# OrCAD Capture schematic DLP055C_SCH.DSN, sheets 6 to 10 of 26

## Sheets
6 P21 - Ballast Connection: size A3
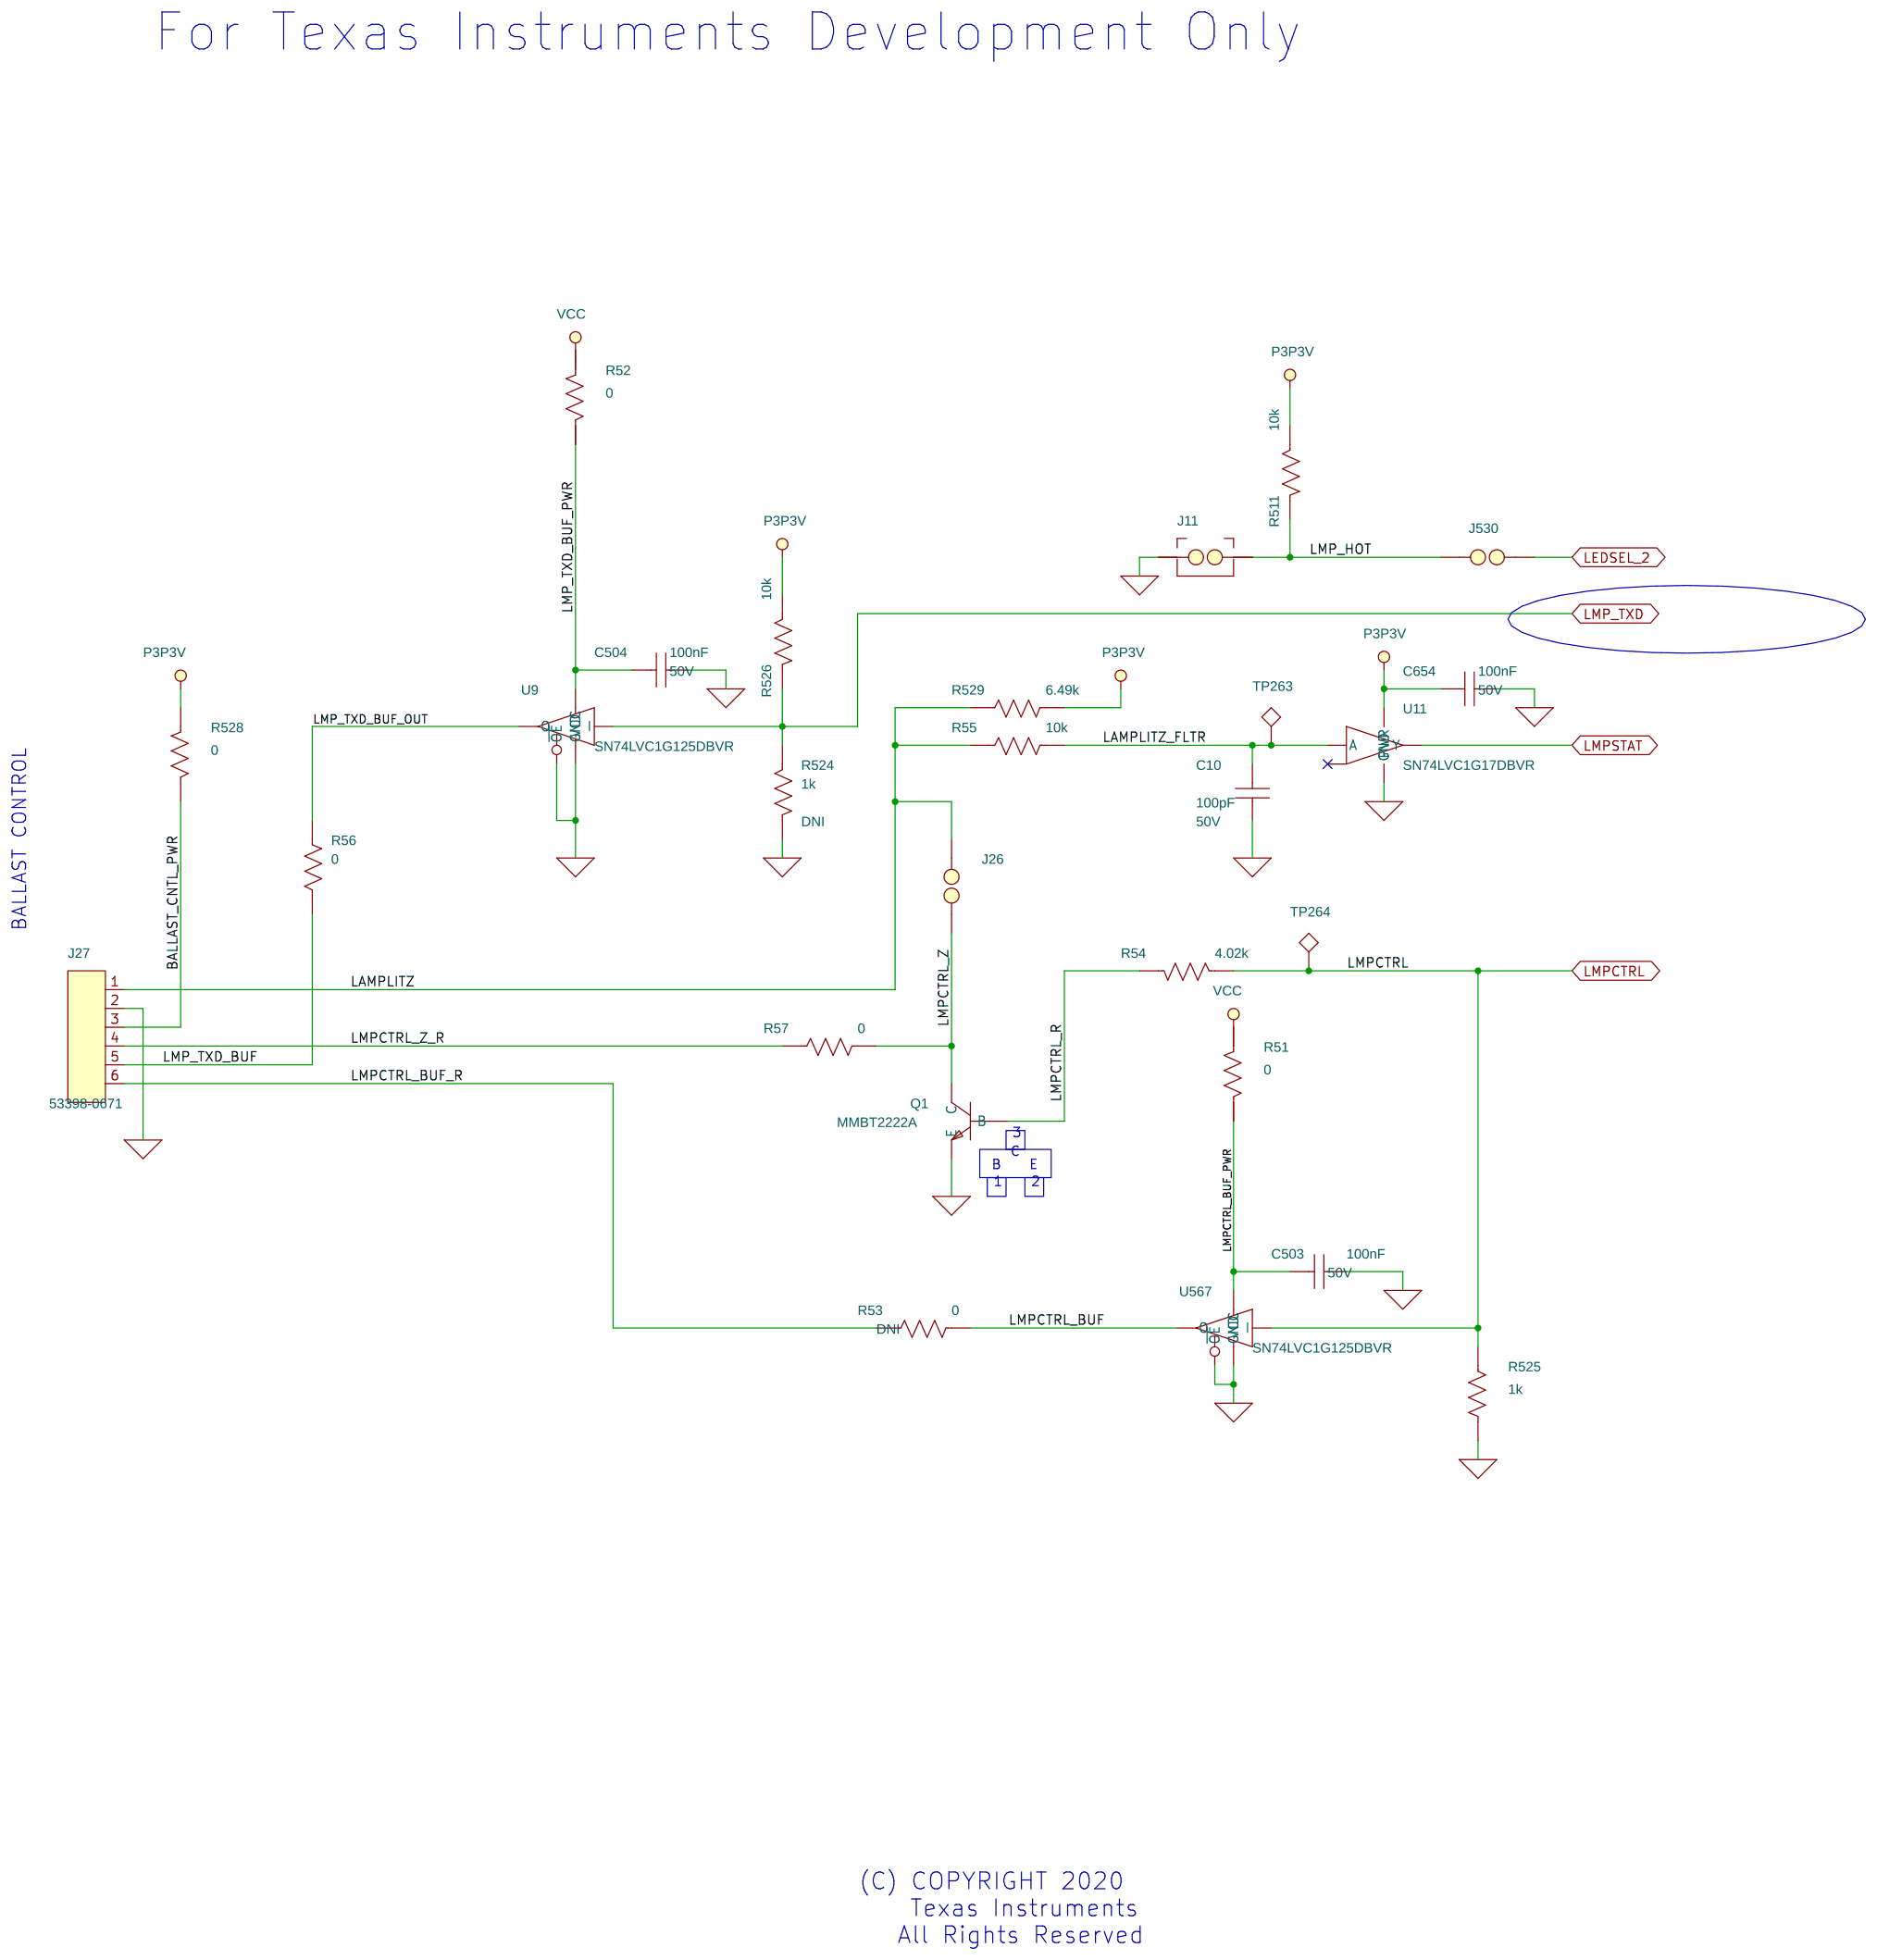
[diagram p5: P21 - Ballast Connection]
7 P19 - VIN & POWER SEQ: size D
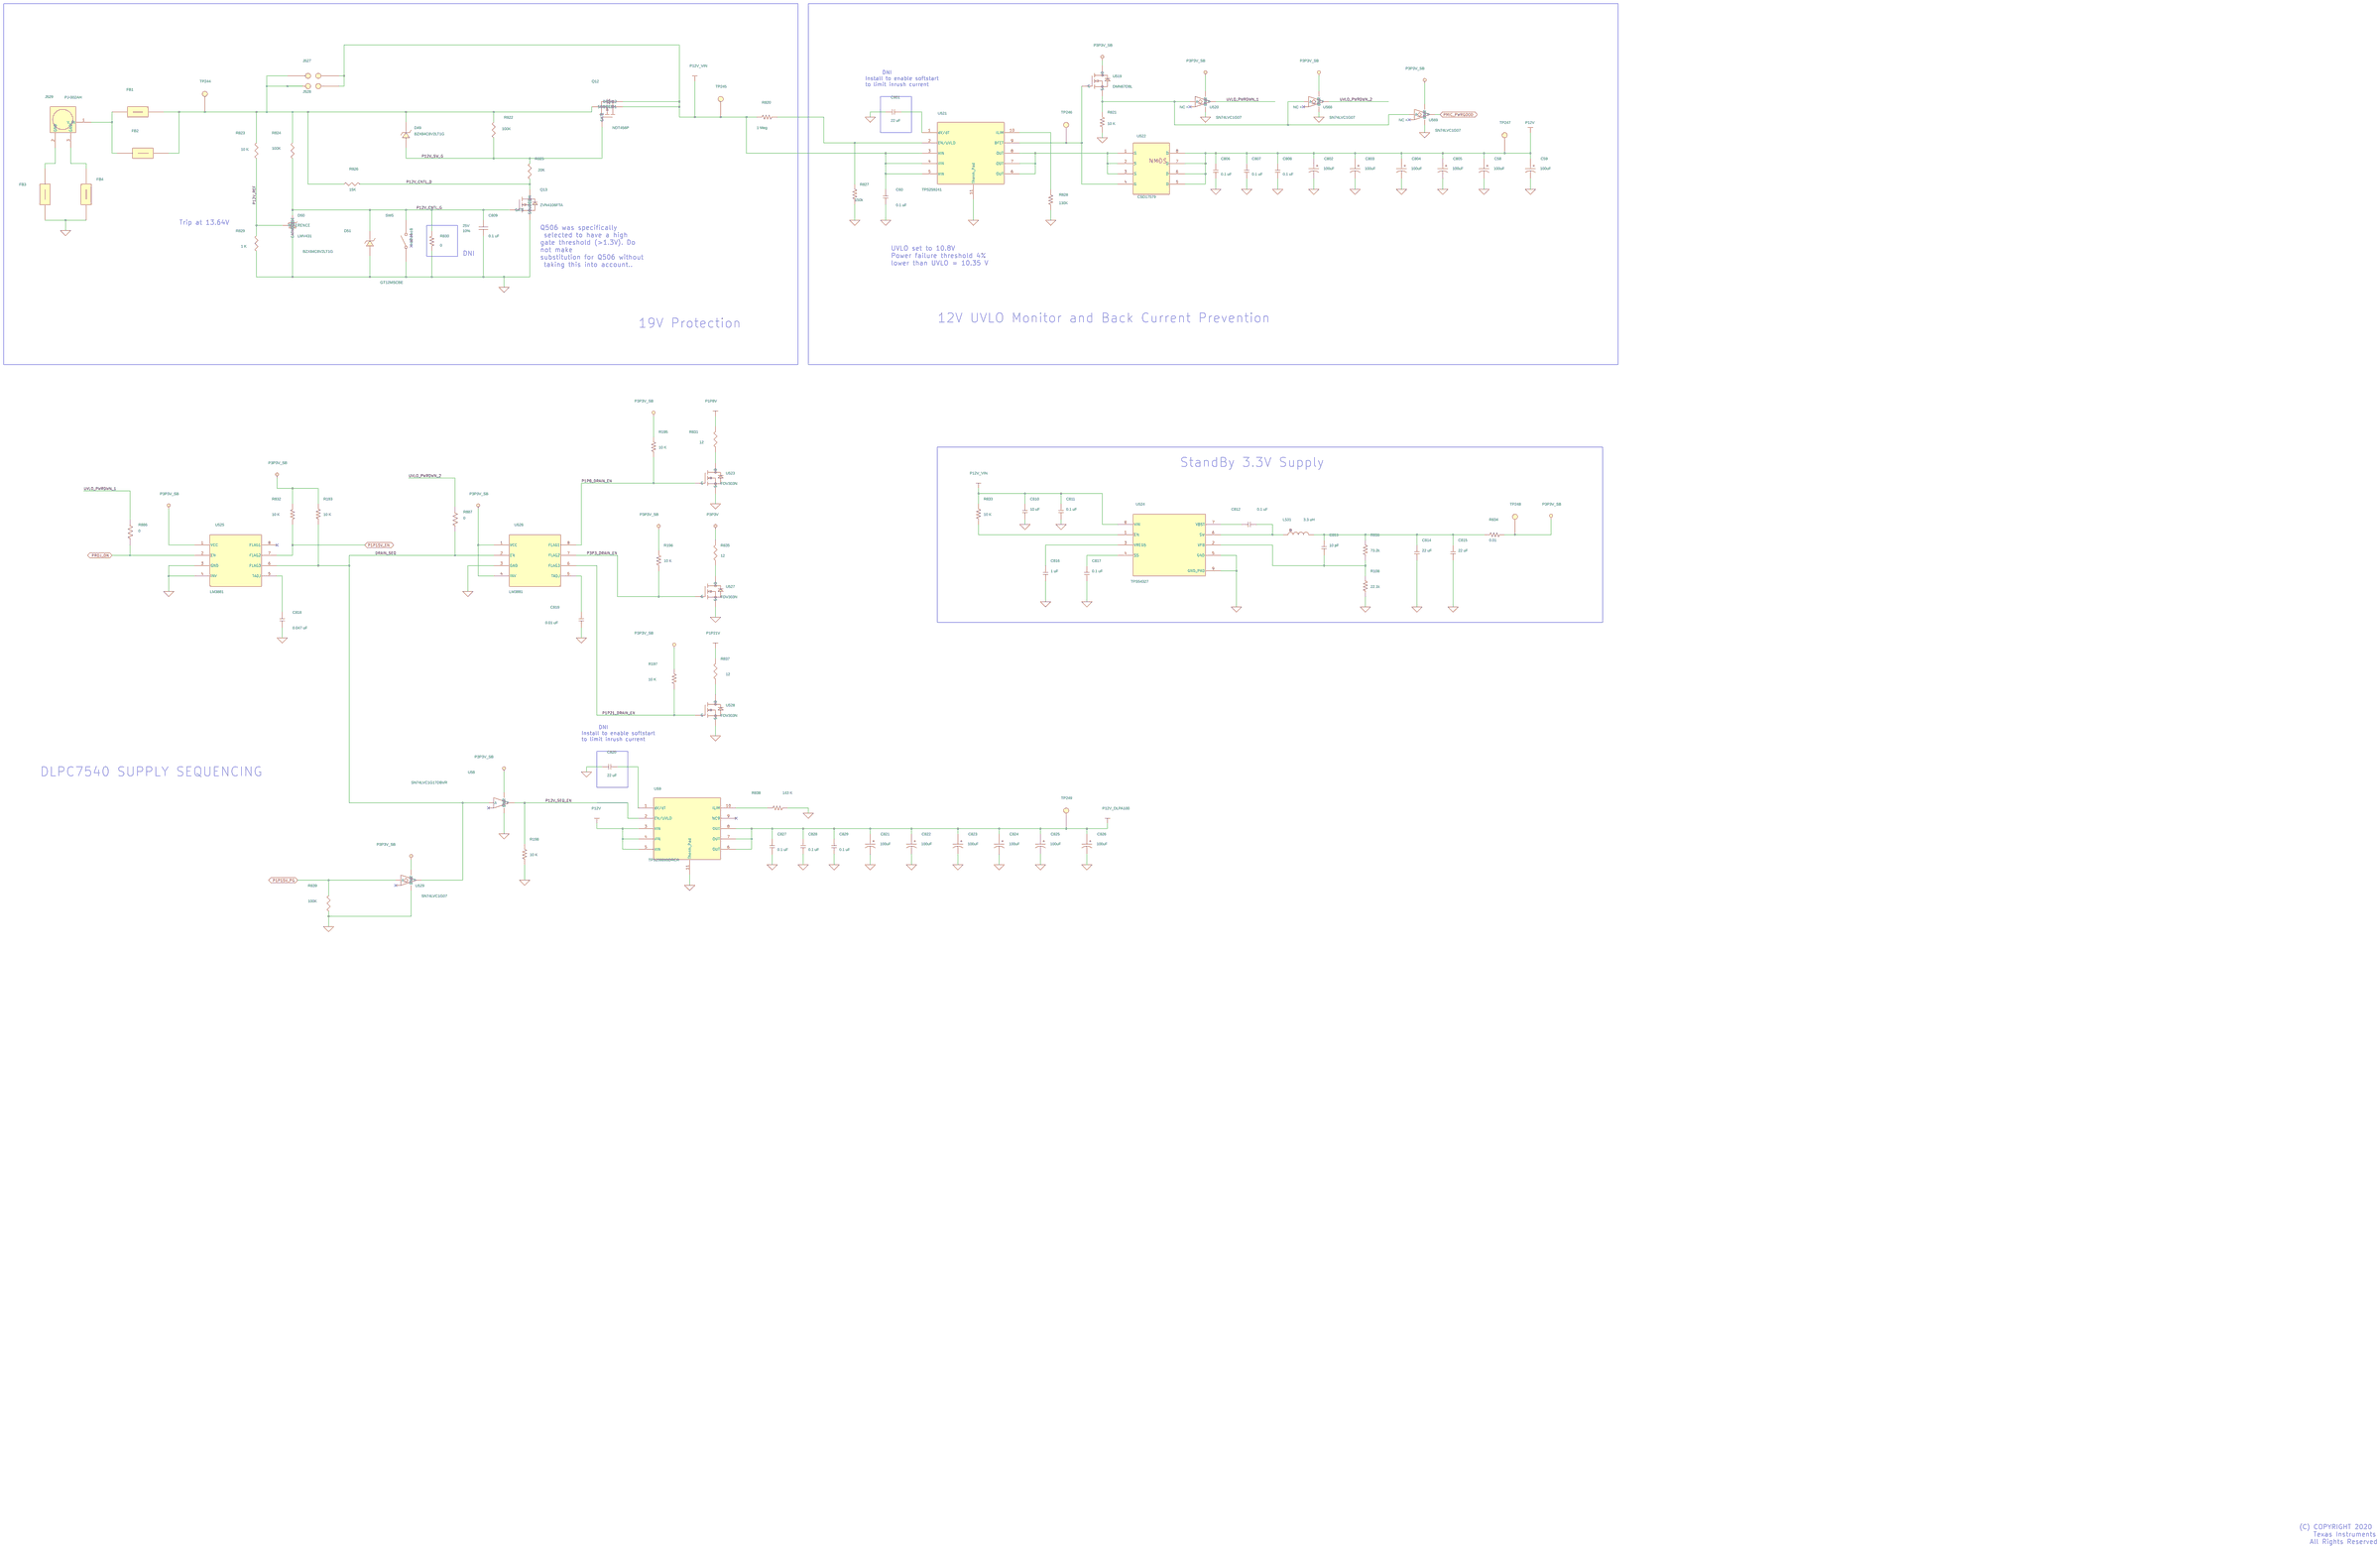
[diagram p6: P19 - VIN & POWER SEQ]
8 P17 - DLPA100 #2: size D
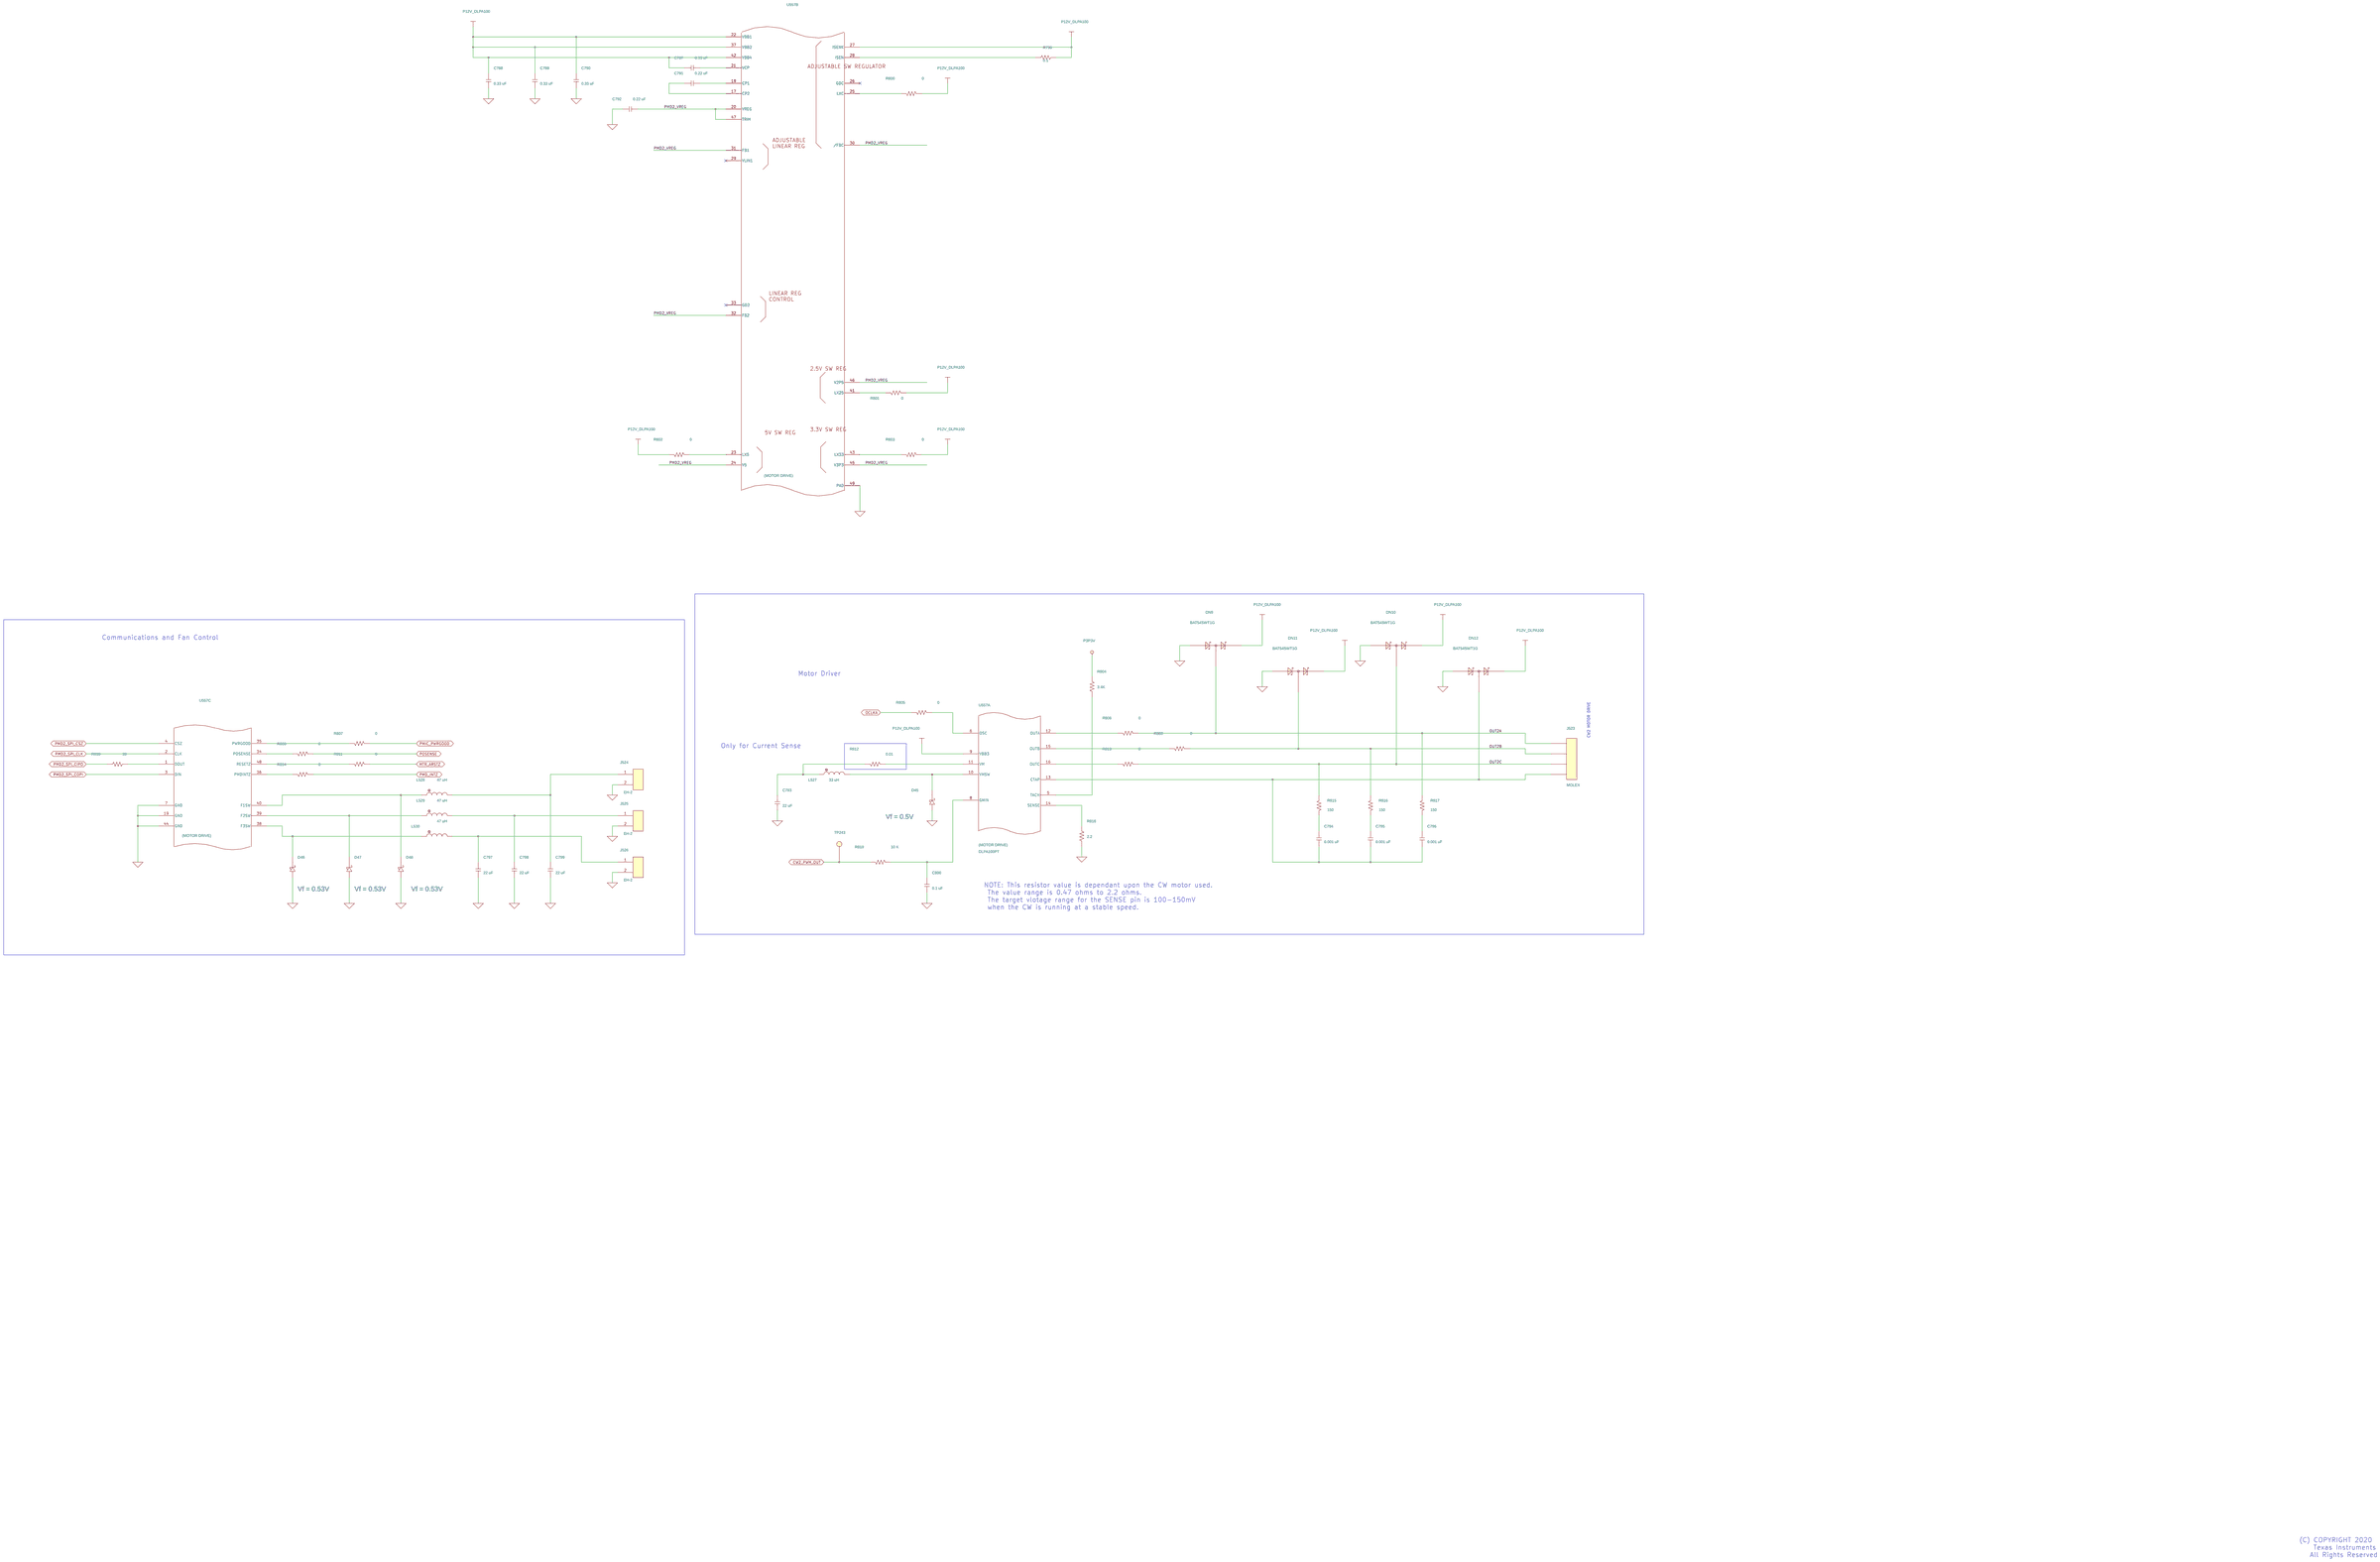
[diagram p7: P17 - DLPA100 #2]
9 P16 - DLPA100 #1: size D
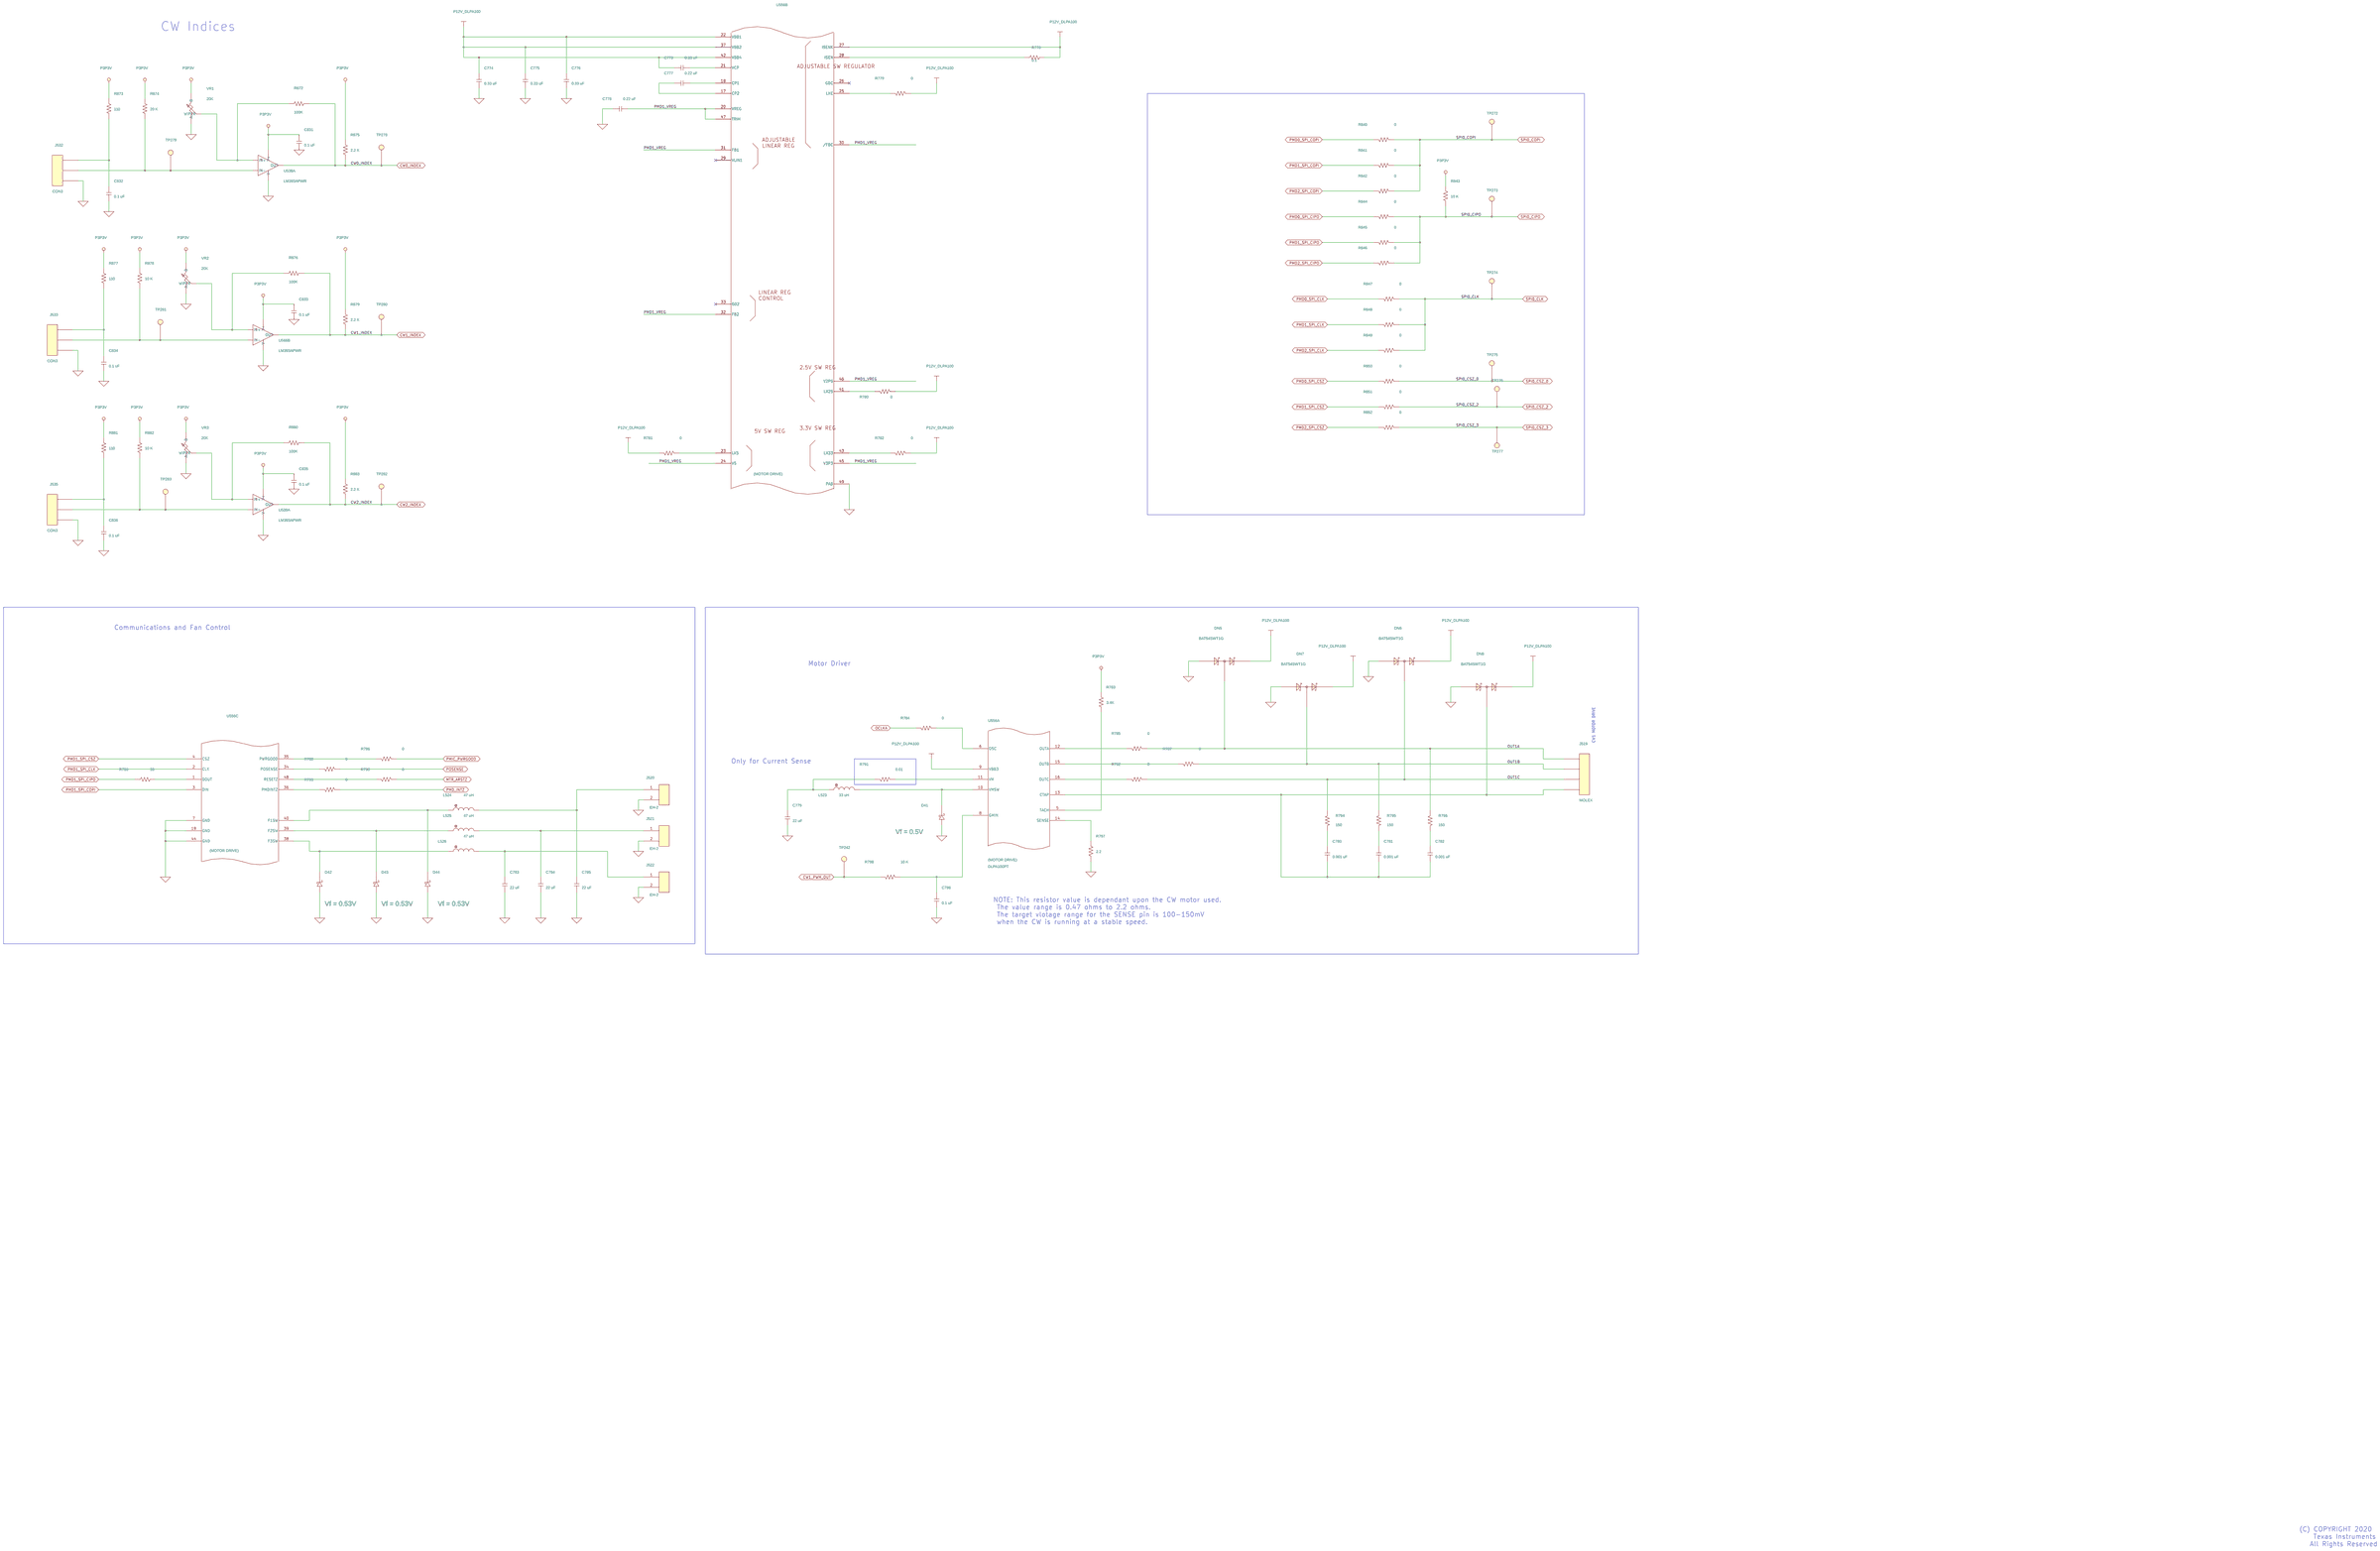
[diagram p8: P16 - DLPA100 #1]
10 P15 - DLPA100 #0: size D
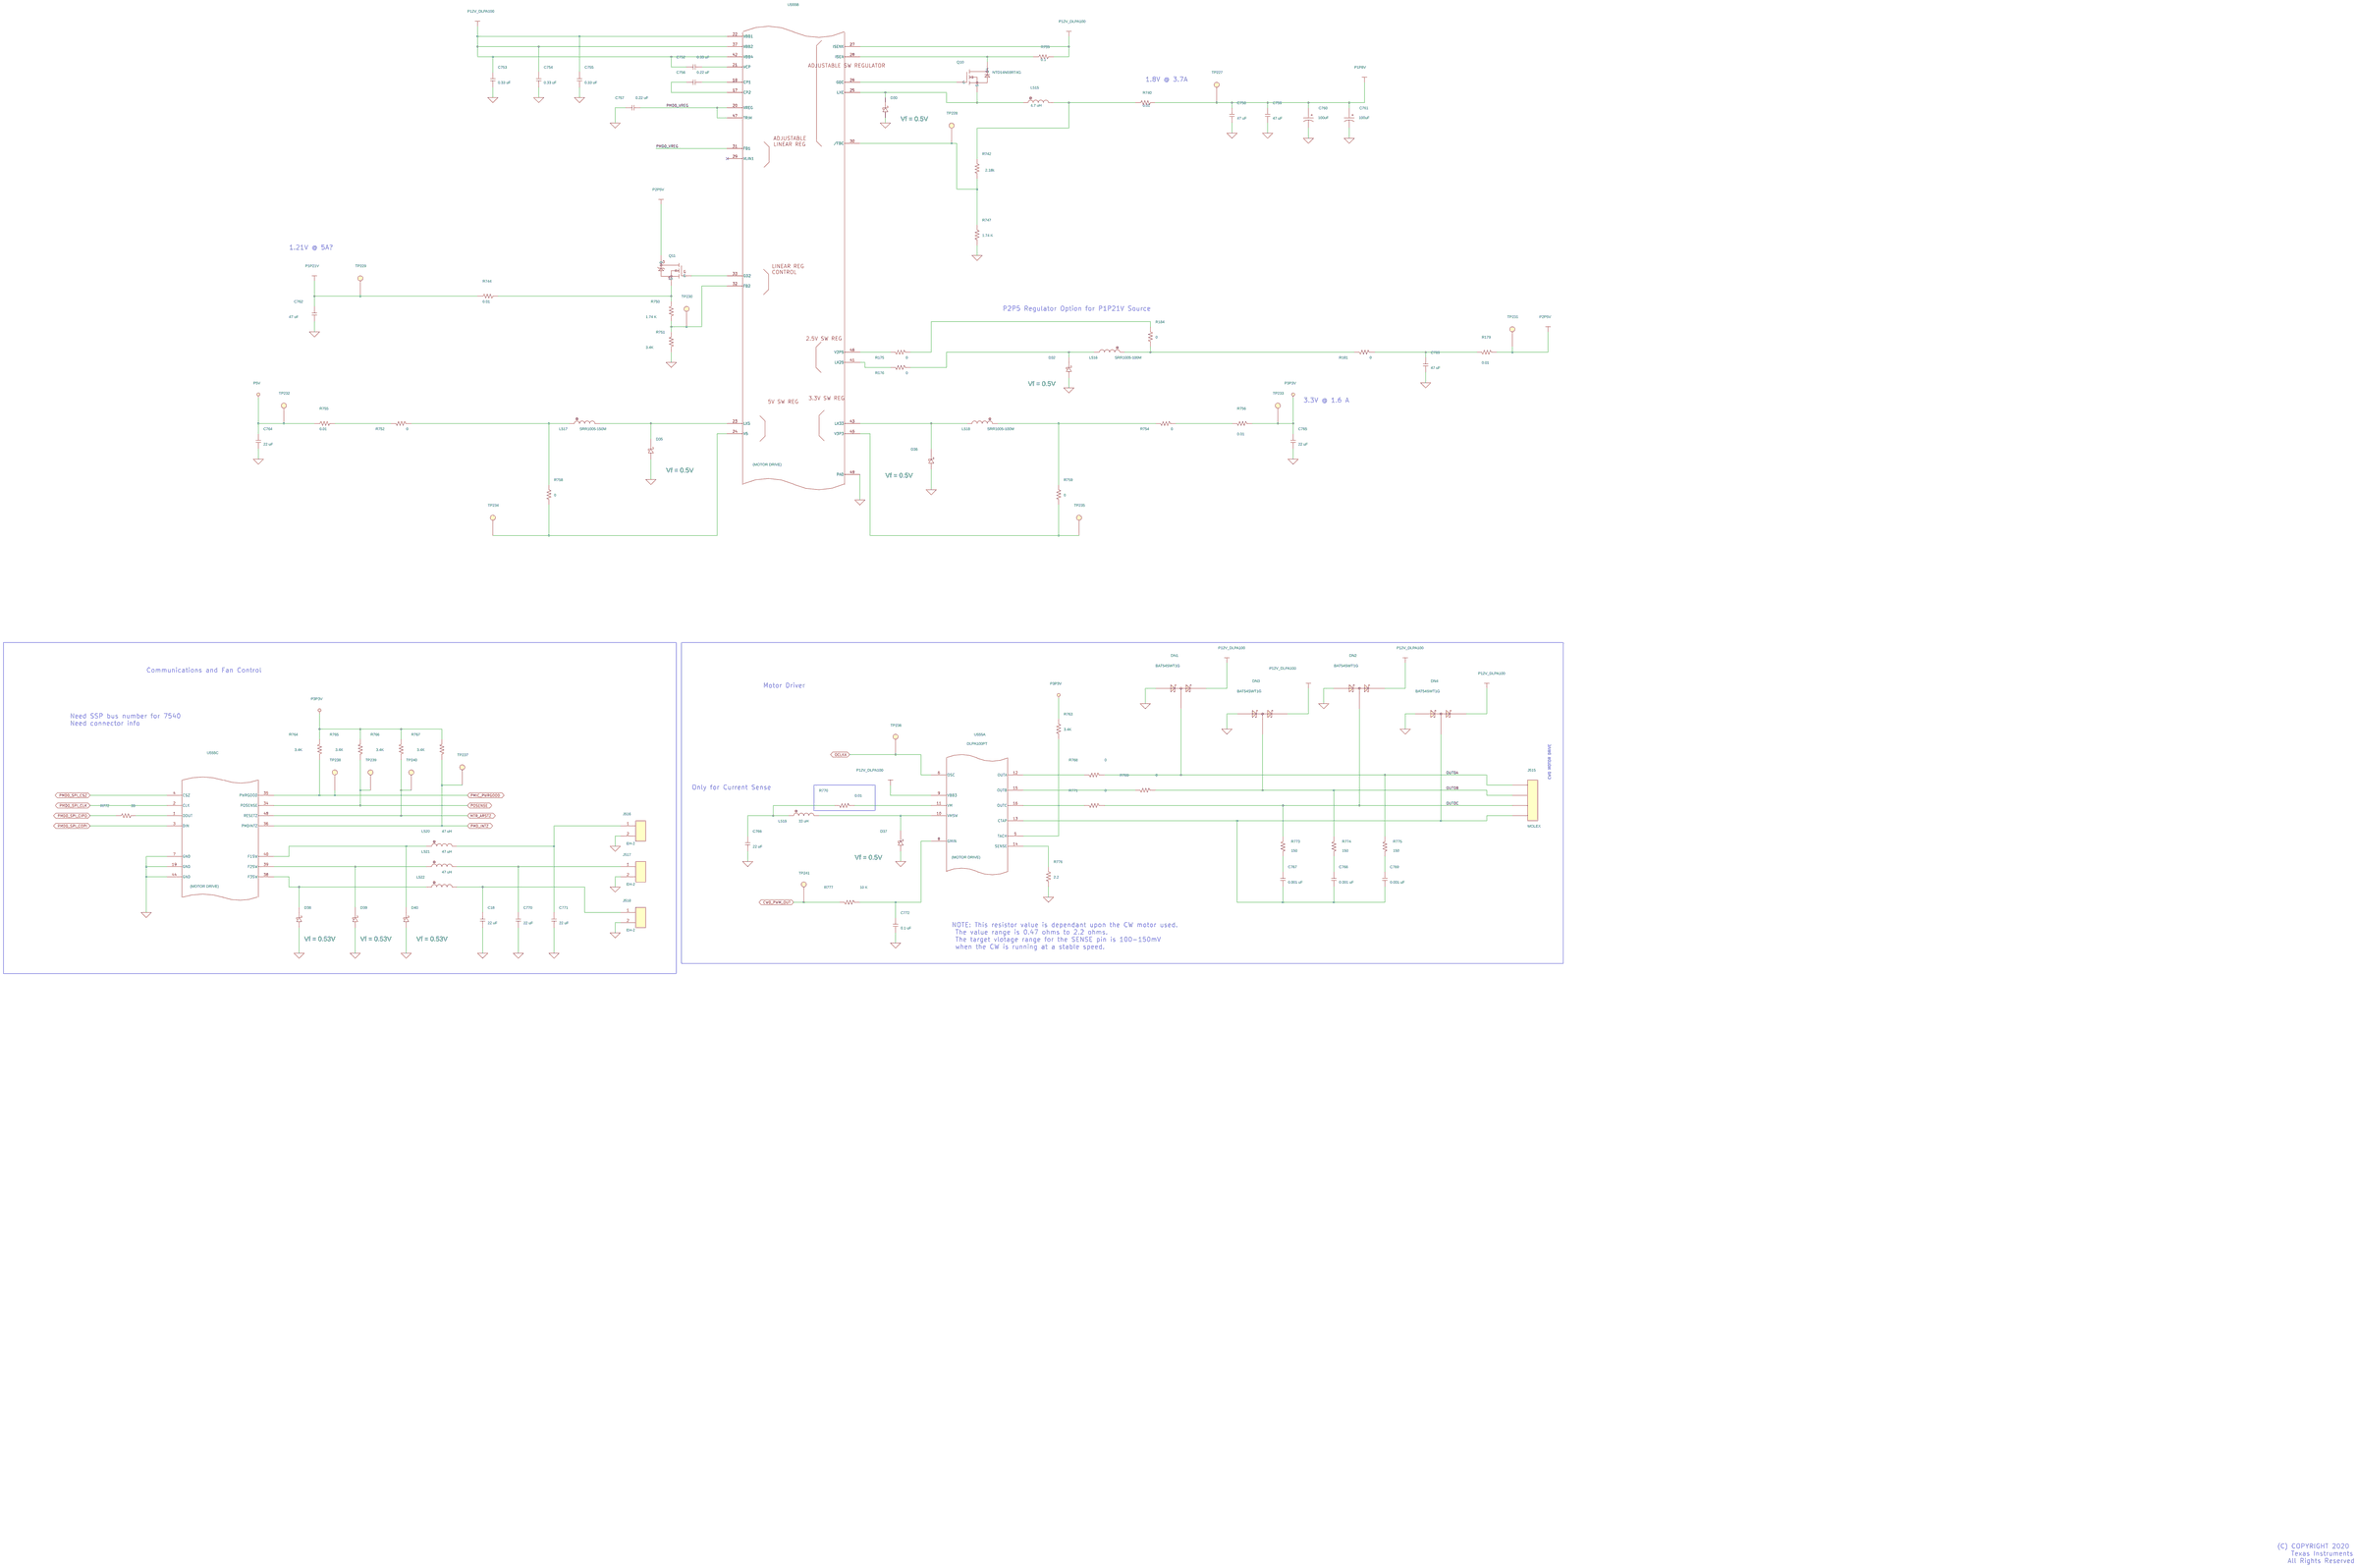
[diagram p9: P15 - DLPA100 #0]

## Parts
sheet P15 - DLPA100 #0
C18  22 uF  [0805]
C752  0.33 uF  [0805]
C753  0.33 uF  [0805]
C754  0.33 uF  [0805]
C755  0.33 uF  [0805]
C756  0.22 uF  [0603]
C757  0.22 uF  [0603]
C758  47 uF  [1206]
C759  47 uF  [1206]
C760  100uF  [7343]
C761  100uF  [7343]
C762  47 uF  [1206]
C763  47 uF  [1206]
C764  22 uF  [0805]
C765  22 uF  [0805]
C766  22 uF  [0805]
C767  0.001 uF  [0603]
C768  0.001 uF  [0603]
C769  0.001 uF  [0603]
C770  22 uF  [0805]
C771  22 uF  [0805]
C772  0.1 uF  [0603]
D30  B220A-13-F  [DIO-SMA_DIO-MOD]
D32  B220A-13-F  [DIO-SMA_DIO-MOD]
D35  B220A-13-F  [DIO-SMA_DIO-MOD]
D36  B220A-13-F  [DIO-SMA_DIO-MOD]
D37  B220A-13-F  [DIO-SMA_DIO-MOD]
D38  B220A-13-F  [DIO-SMA_DIO-MOD]
D39  B220A-13-F  [DIO-SMA_DIO-MOD]
D40  B220A-13-F  [DIO-SMA_DIO-MOD]
DN1  BAT54SWT1G  [SOT-323_SC70_ONSEMI_MOD]
DN2  BAT54SWT1G  [SOT-323_SC70_ONSEMI_MOD]
DN3  BAT54SWT1G  [SOT-323_SC70_ONSEMI_MOD]
DN4  BAT54SWT1G  [SOT-323_SC70_ONSEMI_MOD]
J515  CON4  [CONN4-52808_MOLEX]
J516  EH-2  [CONN2-B2B-EH_JST]
J517  EH-2  [CONN2-B2B-EH_JST]
J518  EH-2  [CONN2-B2B-EH_JST]
L515  4.7 uH  [IND-CDRH104R_SUMIDA]
L516  SRR1005-100M  [IND-SRR1005_BOURNS]
L517  SRR1005-150M  [IND-SRR1005_BOURNS]
L518  SRR1005-100M  [IND-SRR1005_BOURNS]
L519  33 uH  [IND2-74404063330_WURTH]
L520  47 uH  [IND-SRN4018_BOURNS]
L521  47 uH  [IND-SRN4018_BOURNS]
L522  47 uH  [IND-SRN4018_BOURNS]
Q10  NTD14N03RT4G  [DPAK-a]
Q11  NTD14N03RT4G_CUS  [DPAK-a]
R175  0  [0603]
R176  0  [0603]
R179  0.01  [0805wide-KRL2012E_Susumu]
R181  0  [0603]
R184  0  [0603]
R739  0.1  [0805]
R740  0.01  [0805wide-KRL2012E_Susumu]
R742  2.18k  [0603]
R744  0.01  [0805wide-KRL2012E_Susumu]
R747  1.74 K  [0603]
R750  1.74 K  [0603]
R751  3.4K  [0603]
R752  0  [0603]
R754  0  [0603]
R755  0.01  [0805wide-KRL2012E_Susumu]
R756  0.01  [0805wide-KRL2012E_Susumu]
R758  0  [0603]
R759  0  [0603]
R763  3.4K  [0603]
R764  3.4K  [0603]
R765  3.4K  [0603]
R766  3.4K  [0603]
R767  3.4K  [0603]
R768  0  [0603]
R769  0  [0603]
R770  0.01  [0805wide-KRL2012E_Susumu]
R771  0  [0603]
R772  33  [0603]
R773  150  [0603]
R774  150  [0603]
R775  150  [0603]
R776  2.2  [0603]
R777  10 K  [0603]
TP227  Testpoint_via  [TP-30RD12]
TP228  Testpoint_via  [TP-30RD12]
TP229  Testpoint_via  [TP-30RD12]
TP230  Testpoint_via  [TP-30RD12]
TP231  Testpoint_via  [TP-30RD12]
TP232  Testpoint_via  [TP-30RD12]
TP233  Testpoint_via  [TP-30RD12]
TP234  Testpoint_via  [TP-30RD12]
TP235  Testpoint_via  [TP-30RD12]
TP236  Testpoint_via  [TP-30RD12]
TP237  Testpoint_via  [TP-30RD12]
TP238  Testpoint_via  [TP-30RD12]
TP239  Testpoint_via  [TP-30RD12]
TP240  Testpoint_via  [TP-30RD12]
TP241  Testpoint_via  [TP-30RD12]
U555  (MOTOR DRIVE)  [QF48_PPAD-A]  (sections A,B,C)
sheet P16 - DLPA100 #1
C773  0.33 uF  [0805]
C774  0.33 uF  [0805]
C775  0.33 uF  [0805]
C776  0.33 uF  [0805]
C777  0.22 uF  [0603]
C778  0.22 uF  [0603]
C779  22 uF  [0805]
C780  0.001 uF  [0603]
C781  0.001 uF  [0603]
C782  0.001 uF  [0603]
C783  22 uF  [0805]
C784  22 uF  [0805]
C785  22 uF  [0805]
C786  0.1 uF  [0603]
C831  0.1 uF  [0603]
C832  0.1 uF  [0603]
C833  0.1 uF  [0603]
C834  0.1 uF  [0603]
C835  0.1 uF  [0603]
C836  0.1 uF  [0603]
D41  B220A-13-F  [DIO-SMA_DIO-MOD]
D42  B220A-13-F  [DIO-SMA_DIO-MOD]
D43  B220A-13-F  [DIO-SMA_DIO-MOD]
D44  B220A-13-F  [DIO-SMA_DIO-MOD]
DN5  BAT54SWT1G  [SOT-323_SC70_ONSEMI_MOD]
DN6  BAT54SWT1G  [SOT-323_SC70_ONSEMI_MOD]
DN7  BAT54SWT1G  [SOT-323_SC70_ONSEMI_MOD]
DN8  BAT54SWT1G  [SOT-323_SC70_ONSEMI_MOD]
J519  CON4  [CONN4-52808_MOLEX]
J520  EH-2  [CONN2-B2B-EH_JST]
J521  EH-2  [CONN2-B2B-EH_JST]
J522  EH-2  [CONN2-B2B-EH_JST]
J532  CON3  [CONN3-53398-A_MOLEX]
J533  CON3  [CONN3-53398-A_MOLEX]
J535  CON3  [CONN3-53398-A_MOLEX]
L523  33 uH  [IND2-74404063330_WURTH]
L524  47 uH  [IND-SRN4018_BOURNS]
L525  47 uH  [IND-SRN4018_BOURNS]
L526  47 uH  [IND-SRN4018_BOURNS]
R778  0.1  [0805]
R779  0  [0603]
R780  0  [0603]
R781  0  [0603]
R782  0  [0603]
R783  3.4K  [0603]
R784  0  [0603]
R785  0  [0603]
R786  0  [0603]
R787  0  [0603]
R788  0  [0603]
R789  33  [0603]
R790  0  [0603]
R791  0.01  [0805wide-KRL2012E_Susumu]
R792  0  [0603]
R793  0  [0603]
R794  150  [0603]
R795  150  [0603]
R796  150  [0603]
R797  2.2  [0603]
R798  10 K  [0603]
R840  0  [0603]
R841  0  [0603]
R842  0  [0603]
R843  10 K  [0603]
R844  0  [0603]
R845  0  [0603]
R846  0  [0603]
R847  0  [0603]
R848  0  [0603]
R849  0  [0603]
R850  0  [0603]
R851  0  [0603]
R852  0  [0603]
R872  100K  [0603]
R873  110  [0603]
R874  20 K  [0603]
R875  2.2 K  [0603]
R876  100K  [0603]
R877  110  [0603]
R878  10 K  [0603]
R879  2.2 K  [0603]
R880  100K  [0603]
R881  110  [0603]
R882  10 K  [0603]
R883  2.2 K  [0603]
TP242  Testpoint_via  [TP-30RD12]
TP272  Testpoint_via  [TP-30RD12]
TP273  Testpoint_via  [TP-30RD12]
TP274  Testpoint_via  [TP-30RD12]
TP275  Testpoint_via  [TP-30RD12]
TP276  Testpoint_via  [TP-30RD12]
TP277  Testpoint_via  [TP-30RD12]
TP278  Testpoint_via  [TP-30RD12]
TP279  Testpoint_via  [TP-30RD12]
TP280  Testpoint_via  [TP-30RD12]
TP281  Testpoint_via  [TP-30RD12]
TP282  Testpoint_via  [TP-30RD12]
TP283  Testpoint_via  [TP-30RD12]
U538  LM393  [SOIC8-PW_TI]  (section A)
U539  LM393  [SOIC8-PW_TI]  (section A)
U556  (MOTOR DRIVE)  [QF48_PPAD-A]  (sections A,B,C)
U566  LM393  [SOIC8-PW_TI]  (section B)
VR1  20K  [POT-3314G]
VR2  20K  [POT-3314G]
VR3  20K  [POT-3314G]
sheet P17 - DLPA100 #2
C787  0.33 uF  [0805]
C788  0.33 uF  [0805]
C789  0.33 uF  [0805]
C790  0.33 uF  [0805]
C791  0.22 uF  [0603]
C792  0.22 uF  [0603]
C793  22 uF  [0805]
C794  0.001 uF  [0603]
C795  0.001 uF  [0603]
C796  0.001 uF  [0603]
C797  22 uF  [0805]
C798  22 uF  [0805]
C799  22 uF  [0805]
C800  0.1 uF  [0603]
D45  B220A-13-F  [DIO-SMA_DIO-MOD]
D46  B220A-13-F  [DIO-SMA_DIO-MOD]
D47  B220A-13-F  [DIO-SMA_DIO-MOD]
D48  B220A-13-F  [DIO-SMA_DIO-MOD]
DN9  BAT54SWT1G  [SOT-323_SC70_ONSEMI_MOD]
DN10  BAT54SWT1G  [SOT-323_SC70_ONSEMI_MOD]
DN11  BAT54SWT1G  [SOT-323_SC70_ONSEMI_MOD]
DN12  BAT54SWT1G  [SOT-323_SC70_ONSEMI_MOD]
J523  CON4  [CONN4-52808_MOLEX]
J524  EH-2  [CONN2-B2B-EH_JST]
J525  EH-2  [CONN2-B2B-EH_JST]
J526  EH-2  [CONN2-B2B-EH_JST]
L527  33 uH  [IND2-74404063330_WURTH]
L528  47 uH  [IND-SRN4018_BOURNS]
L529  47 uH  [IND-SRN4018_BOURNS]
L530  47 uH  [IND-SRN4018_BOURNS]
R799  0.1  [0805]
R800  0  [0603]
R801  0  [0603]
R802  0  [0603]
R803  0  [0603]
R804  3.4K  [0603]
R805  0  [0603]
R806  0  [0603]
R807  0  [0603]
R808  0  [0603]
R809  0  [0603]
R810  33  [0603]
R811  0  [0603]
R812  0.01  [0805wide-KRL2012E_Susumu]
R813  0  [0603]
R814  0  [0603]
R815  150  [0603]
R816  150  [0603]
R817  150  [0603]
R818  2.2  [0603]
R819  10 K  [0603]
TP243  Testpoint_via  [TP-30RD12]
U557  (MOTOR DRIVE)  [QF48_PPAD-A]  (sections A,B,C)
sheet P19 - VIN & POWER SEQ
C58  100uF  [7343]
C59  100uF  [7343]
C60  0.1 uF  [0603]
C801  22 uF  [0805]
C802  100uF  [7343]
C803  100uF  [7343]
C804  100uF  [7343]
C805  100uF  [7343]
C806  0.1 uF  [0603]
C807  0.1 uF  [0603]
C808  0.1 uF  [0603]
C809  0.1 uF  [0603]
C810  10 uF  [1210]
C811  0.1 uF  [0603]
C812  0.1 uF  [0603]
C813  10 pF  [0603]
C814  22 uF  [0805]
C815  22 uF  [0805]
C816  1 uF  [0603]
C817  0.1 uF  [0603]
C818  0.047 uF  [0402]
C819  0.01 uF  [0402]
C820  22 uF  [0805]
C821  100uF  [7343]
C822  100uF  [7343]
C823  100uF  [7343]
C824  100uF  [7343]
C825  100uF  [7343]
C826  100uF  [7343]
C827  0.1 uF  [0603]
C828  0.1 uF  [0603]
C829  0.1 uF  [0603]
D49  BZX84C8V2LT1G  [SOT-23_ON-SEMI]
D50  LMV431  [SOIC3-DBZ_TI]
D51  BZX84C8V2LT1G  [SOT-23_ON-SEMI]
FB1  FB  [35F0121-1SR-10_LAIRD]
FB2  FB  [35F0121-1SR-10_LAIRD]
FB3  FB  [35F0121-1SR-10_LAIRD]
FB4  FB  [35F0121-1SR-10_LAIRD]
J527  HDR,2P,1R  [HDR2P_1R]
J528  HDR,2P,1R  [HDR2P_1R]
J529  PJ-002AH  [JACK-PJ-002AH_CUI]
L531  3.3 uH  [IND-SRN6045TA_BOURNS]
Q12  NDT456P  [SOT223-a]
Q13  ZVN4106FTA  [SOT23-3_DIO-MOD]
R108  22.1k  [0603]
R193  10 K  [0603]
R195  10 K  [0603]
R196  10 K  [0603]
R197  10 K  [0603]
R198  10 K  [0603]
R820  1 Meg  [0805]
R821  10 K  [0603]
R822  100K  [0603]
R823  10 K  [0603]
R824  100K  [0603]
R825  20K  [0603]
R826  15K  [0603]
R827  150k  [0603]
R828  130K  [0603]
R829  1 K  [0603]
R830  0  [0603]
R831  12  [0805]
R832  10 K  [0603]
R833  10 K  [0603]
R834  0.01  [0805wide-KRL2012E_Susumu]
R835  12  [0805]
R836  73.2k  [0603]
R837  12  [0805]
R838  143 K  [0402]
R839  100K  [0603]
R886  0  [0402]
R887  0  [0402]
SW5  GT12MSCBE  [SW5_GT12MSCBE]
TP244  Testpoint_via  [TP-30RD12]
TP245  Testpoint_via  [TP-30RD12]
TP246  Testpoint_via  [TP-30RD12]
TP247  Testpoint_via  [TP-30RD12]
TP248  Testpoint_via  [TP-30RD12]
TP249  Testpoint_via  [TP-30RD12]
U58  SN74LVC1G17DBVR  [SOIC5-DBV_TI]
U59  TPS259260DRCR  [SOIC10-DRC_TI]
U519  N-CHANNEL MOSFET  [SOT323_DIODESINC]
U520  SN74LVC1G07  [SOIC5-SOT-23_DBV-TI]
U521  TPS259241  [SOIC10-DRC_TI]
U522  CSD17579  [SOIC8-Q5_TI]
U523  N-CHANNEL MOSFET  [SOT23AVX]
U524  TPS54327  [SOIC8-DDA-A_TI]
U525  LM3881  [soic8-dgk_ti]
U526  LM3881  [soic8-dgk_ti]
U527  N-CHANNEL MOSFET  [SOT23AVX]
U528  N-CHANNEL MOSFET  [SOT23AVX]
U529  SN74LVC1G07  [SOIC5-SOT-23_DBV-TI]
U568  SN74LVC1G07  [SOIC5-SOT-23_DBV-TI]
U569  SN74LVC1G07  [SOIC5-SOT-23_DBV-TI]
sheet P21 - Ballast Connection
C10  100pF  [0603]
C503  100nF  [0402]
C504  100nF  [0402]
C654  100nF  [0402]
J11  B2B-EH  [JST_B2B-EH]
J26  HDR,2P,1R  [HDR2P_1R]
J27  53398-0671  [CONN6-53398-0690_MOLEX]
J530  HDR,2P,1R  [HDR2P_1R]
Q1  MMBT2222A  [SOT23]
R51  0  [0402]
R52  0  [0402]
R53  0  [0402]
R54  4.02k  [0603]
R55  10k  [0402]
R56  0  [0402]
R57  0  [0402]
R511  10k  [0402]
R524  1k  [0402]
R525  1k  [0402]
R526  10k  [0402]
R528  0  [0402]
R529  6.49k  [0402]
TP263  Testpoint  [TP-48RD28]
TP264  Testpoint  [TP-48RD28]
U9  TSOP34838  [SOIC5-SOT-23_DBV-TI]
U11  SN74LVC1G17DBVR  [SOIC5-SOT-23_DBV-TI]
U567  TSOP34838  [SOIC5-SOT-23_DBV-TI]

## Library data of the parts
C18 C764-C766 C770 C771 C779 C783-C785 C793 C797-C799 C814 C815 = C: Install: Y; MFG: Samsung; PART NUMBER: CL21A226MAYNNNE; TOLERANCE: 20%; VOLTAGE: 25 V
C752-C755 C773-C776 C787-C790 = C: Install: Y; MFG: Samsung; PART NUMBER: CL21B334KBFNFNE; TOLERANCE: 10%; VOLTAGE: 25 V
C756 C757 C777 C778 C791 C792 = C: Install: Y; MFG: Samsung; PART NUMBER: CL10A224KB8NNNC; TOLERANCE: 10%; VOLTAGE: 25 V
C758 C759 C762 C763 = C: Install: Y; MFG: Samsung; PART NUMBER: CL31A476MPHNNNE; TOLERANCE: 20%; VOLTAGE: 10 V
C58 C59 C760 C761 C802-C805 C821-C826 = CAPACITOR_POL: Install: Y; MFG: Vishay; PART NUMBER: 293D107X9020D2TE3; VOLTAGE: 20V
C767-C769 C780-C782 C794-C796 = C: Install: Y; MFG: Samsung; PART NUMBER: CL10B102KB8NNNC; TOLERANCE: 10%; VOLTAGE: 50 V
C60 C772 C786 C800 C806-C808 C811 C812 C817 C827-C829 C831-C836 = C: Install: Y; MFG: Samsung; PART NUMBER: CL10B104KB8NNNC; TOLERANCE: 10%; VOLTAGE: 50 V
D30 D32 D35-D37 D41 D45 = Schottky_Diode: Install: Y; MFG: Diodes Inc; VOLTAGE: Vf = 0.5V
D38-D40 D42-D44 D46-D48 = Schottky_Diode: Install: Y; MFG: Diodes Inc; VOLTAGE: Vf = 0.53V
DN1-DN12 = DS_DUAL_S_AJK: Diode, Schottky, Dual; Install: Y; MFG: ON Semiconductor; RATING: 30V, 200mA; SOURCE: DIGI BAT54SWT1GOSCT-ND
J515 J519 J523 = CON4_0: Connector, 4 pin, ribbon; Install: Y; MFG: MOLEX; Part Number: 52808-0470; SOURCE: MOUSER 538-52808-0470
J516-J518 J520-J522 J524-J526 = 2pin: Install: Y; MFG: JST; PART NUMBER: B2B-EH-A(LF)(SN)
L515 = L: Install: Y; MFG: Sumida; PART NUMBER: CDRH104RNP-5R2NC; TOLERANCE: 30%
L516-L518 = L: Install: Y; MFG: Bourns
L519 L523 L527 = L: Install: Y; MFG: Wurth Electronics; PART NUMBER: 74404063330; TOLERANCE: 20%
L520-L522 L524-L526 L528-L530 = L: Install: Y; MFG: Bourns; PART NUMBER: SRN4018-470M; TOLERANCE: 20%
Q10 = NTD14NO3RT4_1: Install: Y; MFG: ON Semiconductor
Q11 = NTD14N03RT4G_CUS: Install: Y; MFG: ON SEMICONDUCTOR; Part Number: NTD14N03RT4G
R175 R176 R181 R184 R752 R754 R758 R759 R768 R769 R771 R779-R782 R784-R788 R790 R792 R793 R800-R803 R805-R809 R811 R813 R814 R840-R842 R844-R852 = R: Install: Y; MFG: Panasonic; PART NUMBER: ERJ-3GEY0R00V
R179 R740 R744 R755 R756 R770 R791 R812 R834 = R: Install: Y; MFG: Susumu; PART NUMBER: KRL2012E-M-R010-F-T5; POWER: 1 W
R739 R778 R799 = R: Install: Y; MFG: Samsung; PART NUMBER: RUT2012FR100CS; POWER: 1/4 W; TOLERANCE: 1%
R742 = R: Install: Y; MFG: Yageo; PART NUMBER: RT0603DRD072K18L; POWER: 1/10 W; TOLERANCE: 0.5%
R747 R750 = R: Install: Y; MFG: Panasonic; PART NUMBER: ERJ-PB3D1741V; POWER: 1/5 W; TOLERANCE: 0.5%
R751 R763-R767 R783 R804 = R: Install: Y; MFG: Yageo; PART NUMBER: RT0603DRD073K4L; TOLERANCE: 0.5%
R772 R789 R810 = R: Install: Y; MFG: Panasonic; PART NUMBER: ERJ-3EKF33R0V; POWER: 1/10 W; TOLERANCE: 1%
R773-R775 R794-R796 R815-R817 = R: Install: Y; MFG: Panasonic; PART NUMBER: ERJ-PA3F1500V; POWER: 1/4 W; TOLERANCE: 1%
R776 R797 R818 = R: Install: Y; MFG: Panasonic; PART NUMBER: ERJ-3BQF2R2V; POWER: 1/4 W; TOLERANCE: 1%
R193 R195-R198 R777 R798 R819 R821 R832 R833 R843 R878 R882 = R: Install: Y; MFG: Samsung; PART NUMBER: RC1608F103CS; POWER: 1/10 W; TOLERANCE: 1%
TP227-TP249 TP272-TP283 = Testpoint: Install: DNI; MFG: NOT-A-PART; Notes: 28mil_via; PART NUMBER: NOT-A-PART
U555 = PMD1000_2: Install: Y; MFG: Texas Instruments; PART NUMBER: DLPA100PT; Part Number: DLPA100PT
J532 J533 J535 = CON3_0: Connector, 3 pin; Install: Y; MFG: MOLEX; Part Number: 53398-0371; SOURCE: DIGI WM7607CT-ND
R872 R876 R880 = R: Install: Y; MFG: Panasonic; PART NUMBER: ERJ-3EKF1003V; TOLERANCE: 1%
R873 R877 R881 = R: Install: Y; MFG: Panasonic; PART NUMBER: ERJ-3EKF1100V; TOLERANCE: 1%
R874 = R: Install: Y; MFG: Panasonic; PART NUMBER: ERJ-3EKF2002V; POWER: 1/10 W; TOLERANCE: 1%
R875 R879 R883 = R: Install: Y; MFG: Samsung; PART NUMBER: RC1608F222CS; POWER: 1/10 W; TOLERANCE: 1%
U538 U539 U566 = OPAMP_DUAL: IC, Comparator; Install: Y; MFG: Texas Instruments; Part Number: LM393APWR; SOURCE: DIGI 296-6610-1-ND
U556 U557 = PMD1000_3: Install: Y; MFG: Texas Instruments; PART NUMBER: DLPA100PT; Part Number: DLPA100PT
VR1-VR3 = POT_R_S: IC, Potentiometer; Install: Y; MFG: Bourns; Part Number: 3314G-1-203E; RATING: 1/4W; SOURCE: DIGI 3314G-203ETR-ND; TOLERANCE: 20%
C801 C820 = C: Install: DNI; MFG: Samsung; Notes: DNI; PART NUMBER: CL21A226MAYNNNE; TOLERANCE: 20%; VOLTAGE: 25 V
C809 = CAP_NP: Capacitor; CCA: 48; DigiKey: 490-1524-1-ND; DigiReel: 490-1524-6-ND; Family: passive; Index PN: 234; Install: Y; Lead Style: SMT; MFG: Samsung; Material: x7r; P/D_NUM: GRM188R71E104KA01D; Part Number: CL10B104KB8NNNC; RATING: 25V; SOURCE: DIGI PCC2277CT-ND; TOLERANCE: 10%; Type: capacitor; VOLTAGE: 50 V; VPC: 25V; Vendor: Murata
C810 = C: Install: Y; MFG: Murata; PART NUMBER: GRM32DR61E106KA12L; TOLERANCE: 10%; VOLTAGE: 25 V
C813 = C: Install: Y; MFG: Yageo; PART NUMBER: CC0603KRNPO9BN100; TOLERANCE: 10%; VOLTAGE: 50 V
C816 = C: Install: Y; MFG: AVX; PART NUMBER: 06033D105KAT2A; TOLERANCE: 10%; VOLTAGE: 25 V
C818 = C: Install: Y; MFG: Murata; PART NUMBER: GRM155R71H473KE14D; Rating: 50 V; TOLERANCE: 10%; VOLTAGE: 50 V
C819 = C: Install: Y; MFG: Murata; PART NUMBER: GRM155R71H103KA88J; Rating: 50 V; TOLERANCE: 10%; VOLTAGE: 50 V
D49 D51 = PAS,DIODE,ZENOR,SOT-23,Ap1,Cp3: DigiKey: BZX84C8V2LT1GOSCT-ND; DigiReel: BZX84C8V2LT1GOSDKR-ND; Index PN: 1396; Install: Y; MFG: ON Semiconductor; Part Specific: DIODE ZENER 8.2V 225MW SOT23-3; Type: diode,zener; VPC: 8.2V; Vendor: ON Semiconductor
D50 = PWR,REF,LMV431A,SOT-23: Family: power; Index PN: 1533; Install: Y; Lead Style: SMT; MFG: Texas Instruments; P/D_NUM: LMV431AIMFX/NOPB; Part Number: LMV431AIMFX/NOPB; Type: reference; Vendor: Texas Instruments
FB1-FB4 = Ferrite_Bead_1: Install: Y; MFG: Laird; PART NUMBER: 35F0121-1SR-10
J527 J528 = EM,HDR,2P,1R,2x: DigiKey: 952-2261-ND; DigiReel: ---; Family: electro/mechanical; Index PN: 180; Install: Y; Lead Style: TH; MFG: Harwin; P/D_NUM: M20-9990245; Part Number: M20-9990245; Part Specific: 2 Positions Header, Unshrouded, Breakaway Connector 0.100in (2.54mm) Through Hole Gold; Pin Cnt: 2; Pin Spacing: 100mil; Row Cnt: 1; Type: header; VENDOR: Harwin
J529 = PJ-002AH_0: Install: Y; MFG: CUI
L531 = L: CURRENT: 5A; Install: Y; MFG: Bourns; PART NUMBER: SRN6045TA-3R3Y; TOLERANCE: 30%
Q12 = ANA,MOSFET,P-CH,E,SOT223: Install: Y; MFG: ON Semiconductor
Q13 = ANA,MOSFET,N-CH,E,2N7002,SOT-23: DigiKey: ZVN4106FCT-ND; DigiReel: ---; Family: analog; Index PN: 1587; Lead Style: SMT; MFG: Diodes Incorporated; Part Specific: MOSFET N-CH 60V 200MA SOT23-3; Type: fet; VPC: 60V; Vendor: Diodes Incorporated
R108 = R: Install: Y; MFG: Panasonic; PART NUMBER: ERJ-PB3D2212V; POWER: 1/5 W; TOLERANCE: 0.5%
R820 = R: Install: Y; MFG: Panasonic; PART NUMBER: ERA-6AEB105V; POWER: 1/8 W; TOLERANCE: 0.1%
R822 R824 R839 = PAS,R: DigiKey: 541-100KLCT-ND; DigiReel: 541-100KLDKR-ND; Index PN: 712; Lead Style: SMT; MFG: Panasonic; Material: chip; P/D_NUM: CRCW0402100KFKED; Part Number: ERJ-3EKF1003V; Part Specific: RES 100K OHM 1/10W 1% 0402 SMD; Tolerance: 1%; VPC: 1/16W; Vendor: Vishay/Dale
R823 = PAS,R: DigiKey: 311-10.0KLRCT-ND; DigiReel: 311-10.0KLRDKR-ND; Index PN: 680; Lead Style: SMT; MFG: Samsung; Material: chip; P/D_NUM: RC0402FR-0710KL; POWER: 1/10 W; Part Number: RC1608F103CS; Tolerance: 1%; VPC: 1/16W; Vendor: Yageo
R825 = PAS,R: DigiKey: P20.0KLCT-ND; DigiReel: P20.0KLDKR-ND; Index PN: 1084; Lead Style: SMT; MFG: Panasonic; Material: chip; P/D_NUM: ERJ-2RKF2002X; Part Number: ERJ-3EKF2002V; Part Specific: RES 20.0K OHM 1/10W 1% 0402 SMD; Power: 1/10 W; Tolerance: 1%; VPC: 1/10W; Vendor: Panasonic
R826 = PAS,R: Index PN: 714; MFG: Panasonic; Material: chip; P/D_NUM: ERJ-2RKF1502X; POWER: 1/10 W; Part Number: ERJ-3EKF1502V; Tolerance: 1%; VPC: 1/16W; Vendor: Panasonic
R827 = R: Install: Y; MFG: Panasonic; PART NUMBER: ERJ-3EKF1503V; POWER: 1/10 W; TOLERANCE: 1%
R828 = R: Install: Y; MFG: Yageo; PART NUMBER: RC0603FR-07130KL; POWER: 0.1 W; TOLERANCE: 1%
R829 = PAS,R: DigiKey: 311-1.00KLRCT-ND; DigiReel: 311-1.00KLRDKR-ND; Index PN: 684; Lead Style: SMT; MFG: Panasonic; Material: chip; P/D_NUM: RC0402FR-071KL; POWER: 1/10 W; Part Number: ERJ-3EKF1001V; Part Specific: RES 1.00K OHM 1/10W 1% 0402 SMD; Tolerance: 1%; VPC: 1/16W; Vendor: Yageo
R830 = R: Install: DNI; MFG: Panasonic; Notes: DNI; PART NUMBER: ERJ-3GEY0R00V
R831 R835 R837 = R_v3: Resistor; ALT_SYMBOLS: 0402-1MM; DigiKey Part Number: P12ACT-ND; ICA_MFR_NAME: PANASONIC; ICA_PARTNUM: $$1785048$$ERJ-3GSYJ102; Install: Y; MFG: Panasonic; Part Number: ERJ-6GEYJ120V; RATING: 1/8W; TOLERANCE: 5%
R836 = R: Install: Y; MFG: Panasonic; PART NUMBER: ERA-3AED7322V; TOLERANCE: 0.5%
R838 = R: Install: Y; MFG: Panasonic; PART NUMBER: ERJ-2RKF1433X; POWER: 0.1 W; TOLERANCE: 1%
R886 R887 = PAS,R,large: ALT_SYMBOLS: 0402_1mm; CCA: 62; DigiKey: P0.0JCT-ND; Family: passive; ICA_MFR_NAME: PANASONIC; ICA_PARTNUM: $$1785048$$ERJ-3GSYJ102; Index PN: 687; Install: Y; Lead Style: SMT; MFG: Panasonic; Material: chip; P/D_NUM: ERJ-2GE0R00X; Part Number: ERJ-2GE0R00X; Part Specific: RES 0.0 OHM 1/16W 0402 SMD; Power: 1/16W; Type: resistor; VPC: 1/16W; Vendor: Panasonic
SW5 = SW_SPST_1: Switch; CCA: 122; DigiKey: CKN9050CT-ND; DigiReel: CKN9050DKR-ND; Family: electro/mechanical; Index PN: 1500; Install: Y; Lead Style: SMT; MFG: C&K; Part Specific: SWITCH TOGGLE SPST 0.4VA 20V; SOURCE: DIGI CKN9050TR-ND; Type: switch; Vendor: C&K
U58 = LOG,BUF,SCHMITT_TRIG,1G17_8: DigiKey: 296-11933-1-ND; Family: logic; Index PN: 1495; Lead Style: SMT; MFG: Texas Instruments; Part Specific: IC BUFFER SCHMIT TRIG SOT23-5; Type: buffer
U59 = TPS259260: Install: Y; MFG: Texas Instruments
U519 = N-FET: MOSFET, N-Channel; Install: Y; MFG: Diodes Inc; Part Number: DMN67D8L
U520 U568 U569 = TMP_33: DigiKey: 296-18256-1-ND; MFG: Texas Instruments; MFG PART NUMBER: SN74LVC1G07DBVR; Part Number: SN74LVC1G07DBVR
U521 = TPS259240_0: Install: Y; MFG: Texas Instruments; PART NUMBER: TPS259241DRCT
U522 = CSD17579: Install: Y; MFG: Texas Instruments; PART NUMBER: CSD17579Q5AT
U523 U527 U528 = N-FET: MOSFET, N-Channel; DigiKey Part Number: FDV303NCT-ND; Install: Y; MFG: FAIRCHILD SEMI; Part Number: FDV303N; RATING: 20V; TOLERANCE: 460MW
U524 = TPS54327_0: IC, Switching Voltage Regulator; Install: Y; MFG: Texas Instruments; Part Number: TPS54327DDA
U525 U526 = LM3881: Install: Y; MFG: Texas Instruments; Part Number: LM3881MM/NOPB
U529 = TMP_32: DigiKey: 296-18256-1-ND; MFG: Texas Instruments; MFG PART NUMBER: SN74LVC1G07DBVR; Part Number: SN74LVC1G07DBVR
C10 = PAS,CAP,NP: Capacitor; CCA: 35; DigiKey: 478-1175-1-ND; Digikey Part Number: DIGI 399-1061-2-ND; Family: passive; Index PN: 7; Install: Y; Lead Style: SMT; MFG: AVX; Material: npo; P/D_NUM: 06035A101JAT2A; Part Number: 06035A101JAT2A; RATING: <RATING>; SOURCE: DIGI 399-1061-2-ND; TOLERANCE: 5%; Type: capacitor; VPC: 50V; Vendor: AVX
C503 C504 C654 = PAS,CAP,NP: Capacitor; ALT_SYMBOLS: 0402_1mm; CCA: 34; DigiKey: 587-3499-1-ND; Digikey Part Number: DIGI 399-3520-1-ND; Family: passive; Index PN: 1280; Install: Y; Lead Style: SMT; MFG: Taiyo Yuden; Material: x5r; P/D_NUM: UMK105BJ104KV-F; Part Number: UMK105BJ104KV-F; Part Specific: CAP CER 0.1UF 50V 10% X5R 0402; RATING: <RATING>; SOURCE: DIGI 399-3520-1-ND; TOLERANCE: 10%; Type: capacitor; VPC: 50V; Vendor: Taiyo Yuden
J11 = EM,HDR,2P,1R,1x,B2B_EH,inline: DigiKey: 455-1611-ND; Family: electro/mechanical; Index PN: 1297; Lead Style: TH; MFG: JST; P/D_NUM: B2B-EH-A(LF)(SN); Part Number: B2B-EH-A(LF)(SN); Part Specific: CONN HEADER EH TOP 2POS 2.5MM; Pin Cnt: 3; Pin Spacing: 2.5MM; Row Cnt: 1; Type: header; Vendor: JST
J26 J530 = EM,JMP,2P,1R: DigiKey: 952-2261-ND; Index PN: 180; Lead Style: TH; MFG: Harwin; P/D_NUM: M20-9990245; Part Number: M20-9990245; Part Specific: 2 Positions Header  Unshrouded  Breakaway Connector 0.100in (2.54mm) Through Hole Gold; Pin Cnt: 2; Pin Spacing: 100mil; Row Cnt: 1; Type: header; Vendor: Harwin
J27 = EM,HDR,6P,1R: DigiKey: WM7610CT-ND; Family: electro/mechanical; Index PN: 1521; Install: Y; Lead Style: SMT; MFG: Molex; Part Specific: CONN HEADER 6POS 1.25MM VERT SMD; Pin Cnt: 6; Pin Spacing: 1.25mm; Row Cnt: 1; Type: connector; Vendor: Molex
Q1 = ANA,TRANSISTOR,2N2222A,SOT-23: DigiKey: MMBT2222AFSCT-ND; Family: analog; Index PN: 129; Lead Style: SMT; MFG: ON Semiconductor; Part Specific: Bipolar (BJT) Transistor NPN 40V 1A 300MHz 350mW Surface Mount SOT-23-3; Type: transistor; Vendor: ON Semiconductor
R51 R52 R56 R57 R528 = PAS,R,large: Resistor; ALT_SYMBOLS: 0402_1mm; CCA: 62; DigiKey: P0.0JCT-ND; Digikey Part Number: DIGI P0.0JCT-ND; Family: passive; ICA_MFR_NAME: PANASONIC; ICA_PARTNUM: $$1785048$$ERJ-3GSYJ102; Index PN: 687; Install: Y; Lead Style: SMT; MFG: Panasonic; Material: chip; P/D_NUM: ERJ-2GE0R00X; Part Number: ERJ-2GE0R00X; Part Specific: RES 0.0 OHM 1/16W 0402 SMD; Power: 1/16W; SOURCE: DIGI P0.0JCT-ND; Type: resistor; VPC: 1/16W; Vendor: Panasonic
R53 = PAS,R,large: Resistor; ALT_SYMBOLS: 0402_1mm; CCA: 62; DNI: DNI; DigiKey: P0.0JCT-ND; Digikey Part Number: DIGI P0.0JCT-ND; Family: passive; ICA_MFR_NAME: PANASONIC; ICA_PARTNUM: $$1785048$$ERJ-3GSYJ102; Index PN: 687; Install: DNI; Lead Style: SMT; MFG: Panasonic; Material: chip; P/D_NUM: ERJ-2GE0R00X; Part Number: ERJ-2GE0R00X; Part Specific: RES 0.0 OHM 1/16W 0402 SMD; Power: 1/16W; SOURCE: DIGI P0.0JCT-ND; Type: resistor; VPC: 1/16W; Vendor: Panasonic
R54 = PAS,R,large: Resistor; CCA: 86; DigiKey: P4.02KHCT-ND; Digikey Part Number: DIGI P4.02KHCT-ND; Family: passive; ICA_MFR_NAME: PANASONIC; ICA_PARTNUM: $$1785048$$ERJ-3GSYJ102; Index PN: 1418; Install: Y; Lead Style: SMT; MFG: Panasonic; Material: chip; P/D_NUM: ERJ-3EKF4021V; Part Number: ERJ-3EKF4021V; Part Specific: RES SMD 4.02K OHM 1% 1/10W 0603; SOURCE: DIGI P4.02KHCT-ND; TOLERANCE: 1%; Type: resistor; VPC: 1/10W; Vendor: Panasonic
R55 R511 R526 = PAS,R,large: Resistor; ALT_SYMBOLS: 0402_1mm; CCA: 65; DigiKey: 311-10.0KLRCT-ND; Digikey Part Number: DIGI P10.0KLCT-ND; Family: passive; ICA_MFR_NAME: PANASONIC; ICA_PARTNUM: $$1785048$$ERJ-3GSYJ102; Index PN: 680; Install: Y; Lead Style: SMT; MFG: Yageo; Material: chip; P/D_NUM: RC0402FR-0710KL; Part Number: RC0402FR-0710KL; Power: 1/16W; SOURCE: DIGI P10.0KLCT-ND; TOLERANCE: 1%; Type: resistor; VPC: 1/16W; Vendor: Yageo
R524 = PAS,R,large: Resistor; ALT_SYMBOLS: 0402_1mm; CCA: 64; DNI: DNI; DigiKey: 311-1.00KLRCT-ND; Digikey Part Number: DIGI P1.0KJCT-ND; Family: passive; ICA_MFR_NAME: PANASONIC; ICA_PARTNUM: $$1785048$$ERJ-3GSYJ102; Index PN: 684; Install: DNI; Lead Style: SMT; MFG: Yageo; Material: chip; P/D_NUM: RC0402FR-071KL; Part Number: RC0402FR-071KL; Part Specific: RES 1.00K OHM 1/10W 1% 0402 SMD; Power: 1/16W; SOURCE: DIGI P1.0KJCT-ND; TOLERANCE: 1%; Type: resistor; VPC: 1/16W; Vendor: Yageo
R525 = PAS,R,large: Resistor; ALT_SYMBOLS: 0402_1mm; CCA: 64; DigiKey: 311-1.00KLRCT-ND; Digikey Part Number: DIGI P1.0KJCT-ND; Family: passive; ICA_MFR_NAME: PANASONIC; ICA_PARTNUM: $$1785048$$ERJ-3GSYJ102; Index PN: 684; Install: Y; Lead Style: SMT; MFG: Yageo; Material: chip; P/D_NUM: RC0402FR-071KL; Part Number: RC0402FR-071KL; Part Specific: RES 1.00K OHM 1/10W 1% 0402 SMD; Power: 1/16W; SOURCE: DIGI P1.0KJCT-ND; TOLERANCE: 1%; Type: resistor; VPC: 1/16W; Vendor: Yageo
R529 = PAS,R,large: Resistor; ALT_SYMBOLS: 0402_1mm; CCA: 74; DigiKey: 311-6.49KLRCT-ND; Digikey Part Number: DIGI P6.49KLCT-ND; Family: passive; ICA_MFR_NAME: PANASONIC; ICA_PARTNUM: $$1785048$$ERJ-3GSYJ102; Index PN: 1416; Install: Y; Lead Style: SMT; MFG: Yageo; Material: chip; P/D_NUM: RC0402FR-076K49L; Part Number: RC0402FR-076K49L; Part Specific: RES SMD 6.49K OHM 1% 1/16W 0402; SOURCE: DIGI P6.49KLCT-ND; TOLERANCE: 1%; Type: resistor; VPC: 1/16W; Vendor: Yageo
TP263 TP264 = EM,TERM,TESTPOINT: Test point; Install: DNI; P/D_NUM: -- NOT A PART --; Part Number: -- NOT A PART --
U9 U567 = LOG,BUF,74LVC1G125,1x: DigiKey: 296-11603-1-ND; Family: logic; Index PN: 1496; Lead Style: SMT; MFG: Texas Instruments; P/D_NUM: SN74LVC1G125DBVR; Part Number: SN74LVC1G125DBVR; Part Specific: IC BUS BUFF TRI-ST N-INV SOT23-5; Type: buffer; Vendor: Texas Instruments
U11 = LOG,BUF,SCHMITT_TRIG,1G17_7: DigiKey: 296-11933-1-ND; Family: logic; Index PN: 1495; Lead Style: SMT; MFG: Texas Instruments; Part Specific: IC BUFFER SCHMIT TRIG SOT23-5; Type: buffer

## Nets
GND: C10.1 C18.1 C58.2 C59.2 C60.1 C503.1 C504.1 C654.1 C753.1 C754.1 C755.1 C757.2 C758.2 C759.2 C760.2 C761.2 C762.2 C763.2 C764.1 C765.1 C766.1 C770.1 C771.1 C772.1 C774.1 C775.1 C776.1 C778.2 C779.1 C783.1 C784.1 C785.1 C786.1 C788.1 C789.1 C790.1 C792.2 C793.1 C797.1 C798.1 C799.1 C800.1 C801.2 C802.2 C803.2 C804.2 C805.2 C806.1 C807.1 C808.1 C809.1 C810.1 C811.1 C814.1 C815.1 C816.1 C817.1 C818.1 C819.1 C820.2 C821.2 C822.2 C823.2 C824.2 C825.2 C826.2 C827.1 C828.1 C829.1 C831.1 C832.1 C833.1 C834.1 C835.1 C836.1 D30.1(Anode) D32.1(Anode) D35.1(Anode) D36.1(Anode) D37.1(Anode) D38.1(Anode) D39.1(Anode) D40.1(Anode) D41.1(Anode) D42.1(Anode) D43.1(Anode) D44.1(Anode) D45.1(Anode) D46.1(Anode) D47.1(Anode) D48.1(Anode) D50.3(ANODE) D51.1(ANODE) DN1.1 DN2.1 DN3.1 DN4.1 DN5.1 DN6.1 DN7.1 DN8.1 DN9.1 DN10.1 DN11.1 DN12.1 FB3.1 FB4.1 J11.2 J27.2 J516.2 J517.2 J518.2 J520.2 J521.2 J522.2 J524.2 J525.2 J526.2 J532.3 J533.3 J535.3 Q1.2(E) Q13.2(SOURCE) R108.1 R198.1 R524.1(N1) R525.1(N1) R747.1 R751.1 R776.1 R797.1 R818.1 R821.1 R827.1 R828.2 R829.1 R830.2 R838.2 R839.1 SW5.3 U9.1(~{OE}) U9.3(GND) U11.3(GND) U58.3(GND) U59.11(Therm_Pad) U520.3(GND) U521.11(Therm_Pad) U523.2(S) U524.5(GND) U524.9(GND_PAD) U525.3(GND) U525.4(INV) U526.3(GND) U527.2(S) U528.2(S) U529.3(GND) U538.4(V-) U539.4(V-) U555.7(GND) U555.19(GND) U555.44(GND) U555.49(PAD) U556.7(GND) U556.19(GND) U556.44(GND) U556.49(PAD) U557.7(GND) U557.19(GND) U557.44(GND) U557.49(PAD) U566.4(V-) U567.1(~{OE}) U567.3(GND) U568.3(GND) U569.3(GND) VR1.1(A) VR2.1(A) VR3.1(A) ; also on sheet 3 4 5 11 12 15 16 17 18 19 20 21 22 23 25 26
P5V: C764.2 R755.1 TP232.1 ; also on sheet 3 15 25
P12V: C58.1 C59.1 C802.1 C803.1 C804.1 C805.1 C806.2 C807.2 C808.2 TP247.1 U59.3(VIN) U59.4(VIN) U59.5(VIN) U522.5(D) U522.6(D) U522.7(D) U522.8(D) ; also on sheet 12 17 21 25
P12V_CNTL_D: Q13.3(DRAIN) R825.1 R826.2
P12V_CNTL_G: C809.2 D50.2(CATHODE) D51.3(CATHODE) Q13.1(GATE) R824.1 R830.1 SW5.1
P12V_DLPA100: C752.2 C753.2 C754.2 C755.2 C773.2 C774.2 C775.2 C776.2 C787.2 C788.2 C789.2 C790.2 C821.1 C822.1 C823.1 C824.1 C825.1 C826.1 C827.2 C828.2 C829.2 DN1.2 DN2.2 DN3.2 DN4.2 DN5.2 DN6.2 DN7.2 DN8.2 DN9.2 DN10.2 DN11.2 DN12.2 R739.2 R778.2 R779.1 R780.1 R781.2 R782.1 R799.2 R800.1 R801.1 R802.2 R803.1 TP249.1 U59.6(OUT) U59.7(OUT) U59.8(OUT) U555.9(VBB3) U555.22(VBB1) U555.27(ISENK) U555.37(VBB2) U555.42(VBB4) U556.9(VBB3) U556.22(VBB1) U556.27(ISENK) U556.37(VBB2) U556.42(VBB4) U557.9(VBB3) U557.22(VBB1) U557.27(ISENK) U557.37(VBB2) U557.42(VBB4)
P12V_REF: D50.1(REFERENCE) R823.1 R829.2
P12V_SEQ_EN: R198.2 U58.4(Y) U59.2(EN/UVLO)
P12V_SW_G: D49.1(ANODE) Q12.G(GATE) R822.1 R825.2
P12V_VIN: C60.2 C810.2 C811.2 J527.1 J528.1 Q12.D1(DRAIN1) Q12.D2(DRAIN2) R820.2 R833.2 TP245.1 U521.3(VIN) U521.4(VIN) U521.5(VIN) U524.8(VIN)
BALLAST_CNTL_PWR: J27.3 R528.2(N2)
CW0_INDEX: R872.1 R875.1 TP278.1 U538.1(OUT) ; also on sheet 18
CW0_PWM_OUT: R777.2 TP241.1 ; also on sheet 18
CW1_INDEX: R876.1 R879.1 TP280.1 U566.7(OUT) ; also on sheet 20
CW1_PWM_OUT: R798.2 TP242.1 ; also on sheet 20
CW2_INDEX: R880.1 R883.1 TP282.1 U539.1(OUT) ; also on sheet 20
CW2_PWM_OUT: R819.2 TP243.1 ; also on sheet 20
DRAIN_SEQ: R193.1 R887.2(N2) U58.2(A) U525.6(FLAG3) U526.2(EN) U529.4(Y)
LAMPLITZ: J26.1 J27.1 R55.2(N2) R529.2(N2)
LAMPLITZ_FLTR: C10.2 R55.1(N1) TP263.1(P1) U11.2(A)
LEDSEL_2: J530.2 ; also on sheet 20 25
LMP_HOT: J11.1 J530.1 R511.1(N1)
LMP_TXD: R524.2(N2) R526.1(N1) U9.2(I) ; also on sheet 20
LMP_TXD_BUF: J27.5 R56.2(N2)
LMP_TXD_BUF_OUT: R56.1(N1) U9.4(O)
LMP_TXD_BUF_PWR: C504.2 R52.2(N2) U9.5(VCC)
LMPCTRL: R54.2(N2) R525.2(N2) TP264.1(P1) U567.2(I) ; also on sheet 20 25
LMPCTRL_BUF: R53.1(N1) U567.4(O)
LMPCTRL_BUF_PWR: C503.2 R51.2(N2) U567.5(VCC)
LMPCTRL_BUF_R: J27.6 R53.2(N2)
LMPCTRL_R: Q1.1(B) R54.1(N1)
LMPCTRL_Z: J26.2 Q1.3(C) R57.1(N1)
LMPCTRL_Z_R: J27.4 R57.2(N2)
LMPSTAT: U11.4(Y) ; also on sheet 20
MTR_ARSTZ: R766.1 R790.1 R811.1 TP240.1 U555.48(RESETZ) ; also on sheet 18
OCLKA: R784.2 R805.2 TP236.1 U555.6(OSC) ; also on sheet 18
OUT0A: DN1.3 J515.4 R768.1 R775.1
OUT0B: DN3.3 J515.3 R769.1 R774.1
OUT0C: DN2.3 J515.2 R771.1 R773.1
OUT1A: DN5.3 J519.4 R785.1 R796.1
OUT1B: DN7.3 J519.3 R787.1 R795.1
OUT1C: DN6.3 J519.2 R792.1 R794.1
OUT2A: DN9.3 J523.4 R806.1 R817.1
OUT2B: DN11.3 J523.3 R808.1 R816.1
OUT2C: DN10.3 J523.2 R813.1 R815.1
P1P8_DRAIN_EN: R195.1 U523.1(G) U526.8(FLAG1)
P1P8V: C758.1 C759.1 C760.1 C761.1 R740.2 R831.1 TP227.1 ; also on sheet 20 22
P1P15V_EN: R832.2 U525.7(FLAG2) ; also on sheet 21
P1P15V_PG: R839.2 U529.2(A) ; also on sheet 21
P1P21_DRAIN_EN: R197.1 U526.6(FLAG3) U528.1(G)
P1P21V: C762.1 R744.1 R837.1 TP229.1 ; also on sheet 22
P2P5V: Q11.4(D) R179.1 TP231.1
P3P3_DRAIN_EN: R196.1 U526.7(FLAG2) U527.1(G)
P3P3V: C654.2 C765.2 C831.2 C833.2 C835.2 R51.1(N1) R52.1(N1) R511.2(N2) R526.2(N2) R528.1(N1) R529.1(N1) R756.1 R763.2 R764.2 R765.2 R766.2 R767.2 R783.2 R804.2 R835.1 R843.2 R873.2 R874.2 R875.2 R877.2 R878.2 R879.2 R881.2 R882.2 R883.2 TP233.1 U11.5(PWR) U538.8(V+) U539.8(V+) U566.8(V+) VR1.3(B) VR2.3(B) VR3.3(B) ; also on sheet 4 11 12 15 16 18 19 20 21 22 25 26
P3P3V_SB: R193.2 R195.2 R196.2 R197.2 R832.1 R834.2 TP248.1 U58.5(PWR) U519.3(D) U520.5(PWR) U525.1(VCC) U526.1(VCC) U526.4(INV) U529.5(PWR) U568.5(PWR) U569.5(PWR) ; also on sheet 4 5 19 21
PMD0_SPI_CIPO: R772.1 R844.2
PMD0_SPI_CLK: R847.2 U555.2(CLK)
PMD0_SPI_COPI: R840.2 U555.3(DIN)
PMD0_SPI_CSZ: R850.2 U555.4(CSZ)
PMD0_VREG: C757.1 U555.20(VREG) U555.31(FB1) U555.47(TRIM)
PMD1_SPI_CIPO: R789.1 R845.2
PMD1_SPI_CLK: R848.2 U556.2(CLK)
PMD1_SPI_COPI: R841.2 U556.3(DIN)
PMD1_SPI_CSZ: R851.2 U556.4(CSZ)
PMD1_VREG: C778.1 U556.20(VREG) U556.24(V5) U556.30(/FBC) U556.31(FB1) U556.32(FB2) U556.45(V3P3) U556.46(V2P5) U556.47(TRIM)
PMD2_SPI_CIPO: R810.1 R846.2
PMD2_SPI_CLK: R849.2 U557.2(CLK)
PMD2_SPI_COPI: R842.2 U557.3(DIN)
PMD2_SPI_CSZ: R852.2 U557.4(CSZ)
PMD2_VREG: C792.1 U557.20(VREG) U557.24(V5) U557.30(/FBC) U557.31(FB1) U557.32(FB2) U557.45(V3P3) U557.46(V2P5) U557.47(TRIM)
PMD_INTZ: R767.1 R793.1 R814.1 TP237.1 U555.36(PMDINTZ) ; also on sheet 18
PMIC_PWRGOOD: R764.1 R786.1 R807.1 TP238.1 U555.35(PWRGOOD) U569.4(Y) ; also on sheet 21
POSENSE: R765.1 R788.1 R809.1 TP239.1 U555.34(POSENSE) ; also on sheet 16 18 21
PROJ_ON: R886.2(N2) U525.2(EN) ; also on sheet 21
SPI0_CIPO: R843.1 R844.1 R845.1 R846.1 TP273.1 ; also on sheet 12 18 19
SPI0_CLK: R847.1 R848.1 R849.1 TP274.1 ; also on sheet 12 18 19
SPI0_COPI: R840.1 R841.1 R842.1 TP272.1 ; also on sheet 12 18 19
SPI0_CSZ_0: R850.1 TP275.1 ; also on sheet 18 19
SPI0_CSZ_2: R851.1 TP276.1 ; also on sheet 18
SPI0_CSZ_3: R852.1 TP277.1 ; also on sheet 20
UVLO_PWRDWN_1: R886.1(N1) U520.4(Y)
UVLO_PWRDWN_2: R887.1(N1) U568.4(Y)
N30120583: Q10.4(D4) R739.1 U555.28(ISEN)
N30120605: C752.1 U555.21(VCP)
N30120666: C756.2 U555.17(CP2)
N30120670: C756.1 U555.18(CP1)
N30120672: Q10.1(G) U555.26(GDC)
N30120689: D30.2(Cathode) L515.1 Q10.3(S) U555.25(LXC)
N30120771: L515.2 R740.1 R742.2
N30120877: R742.1 R747.2 TP228.1 U555.30(/FBC)
N30121099: Q11.1(G) U555.33(GD2)
N30121105: Q11.3(S) R744.2 R750.2
N30121107: R750.1 R751.2 TP230.1 U555.32(FB2)
N30121177: R175.1 R184.2
N30121238: L516.1 R181.2 R184.1
N30121260: R175.2 U555.46(V2P5)
N30121264: D32.2(Cathode) L516.2 R176.1
N30121280: C763.1 R179.2 R181.1
N30121294: R176.2 U555.41(LX25)
N30121351: L517.1 R752.1 R758.2
N30121367: L518.1 R754.2 R759.2
N30121371: R754.1 R756.2
N30121469: R752.2 R755.2
N30121485: D35.2(Cathode) L517.2 U555.23(LX5)
N30121491: D36.2(Cathode) L518.2 U555.43(LX33)
N30121519: R758.1 TP234.1 U555.24(V5)
N30121523: R759.1 TP235.1 U555.45(V3P3)
N30121878: C767.1 C768.1 C769.1 DN4.3 J515.1 U555.13(CTAP)
N30121880: R763.1 U555.5(TACH)
N30122104: R768.2 U555.12(OUTA)
N30122184: R769.2 U555.15(OUTB)
N30122241: C766.2 L519.1 R770.2
N30122253: R770.1 U555.11(VM)
N30122255: R771.2 U555.16(OUTC)
N30122286: R772.2 U555.1(DOUT)
N30122298: D37.2(Cathode) L519.2 U555.10(VMSW)
N30122348: C771.2 J516.1 L520.2
N30122394: C772.2 R777.1 U555.8(GMIN)
N30122422: D40.2(Cathode) L520.1 U555.40(F1SW)
N30122436: R776.2 U555.14(SENSE)
N30122458: C767.2 R773.2
N30122460: C768.2 R774.2
N30122462: C769.2 R775.2
N30122488: D39.2(Cathode) L521.1 U555.39(F2SW)
N30122494: C770.2 J517.1 L521.2
N30122512: D38.2(Cathode) L522.1 U555.38(F3SW)
N30122563: C18.2 J518.1 L522.2
N30125467: R778.1 U556.28(ISEN)
N30125481: C773.1 U556.21(VCP)
N30125519: C777.2 U556.17(CP2)
N30125523: C777.1 U556.18(CP1)
N30125543: R779.2 U556.25(LXC)
N30125602: R780.2 U556.41(LX25)
N30125636: R781.1 U556.23(LX5)
N30125638: R782.2 U556.43(LX33)
N30125770: C780.1 C781.1 C782.1 DN8.3 J519.1 U556.13(CTAP)
N30125772: R783.1 U556.5(TACH)
N30125789: R784.1 U556.6(OSC)
N30125944: R785.2 U556.12(OUTA)
N30126008: R786.2 U556.35(PWRGOOD)
N30126042: R787.2 U556.15(OUTB)
N30126057: R788.2 U556.34(POSENSE)
N30126109: R789.2 U556.1(DOUT)
N30126111: R790.2 U556.48(RESETZ)
N30126115: C779.2 L523.1 R791.2
N30126127: R791.1 U556.11(VM)
N30126129: R792.2 U556.16(OUTC)
N30126176: R793.2 U556.36(PMDINTZ)
N30126180: C785.2 J520.1 L524.2
N30126190: D41.2(Cathode) L523.2 U556.10(VMSW)
N30126220: D44.2(Cathode) L524.1 U556.40(F1SW)
N30126261: C786.2 R798.1 U556.8(GMIN)
N30126303: R797.2 U556.14(SENSE)
N30126331: D43.2(Cathode) L525.1 U556.39(F2SW)
N30126337: C784.2 J521.1 L525.2
N30126343: C780.2 R794.2
N30126345: C781.2 R795.2
N30126347: C782.2 R796.2
N30126360: D42.2(Cathode) L526.1 U556.38(F3SW)
N30126390: C783.2 J522.1 L526.2
N30128088: R799.1 U557.28(ISEN)
N30128102: C787.1 U557.21(VCP)
N30128140: C791.2 U557.17(CP2)
N30128144: C791.1 U557.18(CP1)
N30128164: R800.2 U557.25(LXC)
N30128223: R801.2 U557.41(LX25)
N30128257: R802.1 U557.23(LX5)
N30128259: R803.2 U557.43(LX33)
N30128391: C794.1 C795.1 C796.1 DN12.3 J523.1 U557.13(CTAP)
N30128393: R804.1 U557.5(TACH)
N30128410: R805.1 U557.6(OSC)
N30128565: R806.2 U557.12(OUTA)
N30128629: R807.2 U557.35(PWRGOOD)
N30128663: R808.2 U557.15(OUTB)
N30128678: R809.2 U557.34(POSENSE)
N30128730: R810.2 U557.1(DOUT)
N30128732: R811.2 U557.48(RESETZ)
N30128736: C793.2 L527.1 R812.2
N30128748: R812.1 U557.11(VM)
N30128750: R813.2 U557.16(OUTC)
N30128797: R814.2 U557.36(PMDINTZ)
N30128801: C799.2 J524.1 L528.2
N30128811: D45.2(Cathode) L527.2 U557.10(VMSW)
N30128841: D48.2(Cathode) L528.1 U557.40(F1SW)
N30128882: C800.2 R819.1 U557.8(GMIN)
N30128924: R818.2 U557.14(SENSE)
N30128952: D47.2(Cathode) L529.1 U557.39(F2SW)
N30128958: C798.2 J525.1 L529.2
N30128964: C794.2 R815.2
N30128966: C795.2 R816.2
N30128968: C796.2 R817.2
N30128978: D46.2(Cathode) L530.1 U557.38(F3SW)
N30129011: C797.2 J526.1 L530.2
N30131580: D49.3(CATHODE) FB1.2 FB2.2 J527.2 J528.2 Q12.S(SOURCE) R822.2 R823.2 R824.2 R826.1 TP244.1
N30131609: TP246.1 U519.1(G) U521.9(BFET) U522.4(G)
N30131654: R821.2 U519.2(S) U520.2(A) U568.2(A) U569.2(A)
N30131717: FB1.1 FB2.1 J529.1(V_IN)
N30131761: C801.1 U521.1(dV/dT)
N30131777: R820.1 R827.2 U521.2(EN/UVLO)
N30131888: R828.1 U521.10(ILIM)
N30131961: FB3.2 J529.2(GND)
N30131963: FB4.2 J529.3(GND)
N30131977: U521.6(OUT) U521.7(OUT) U521.8(OUT) U522.1(S) U522.2(S) U522.3(S)
N30132461: R831.2 U523.3(D)
N30132672: R833.1 U524.1(EN)
N30132680: C812.2 U524.7(VBST)
N30132682: C812.1 L531.1 U524.6(SW)
N30132740: C813.2 C814.2 C815.2 L531.2 R834.1 R836.2
N30132787: C816.2 U524.3(VREG5)
N30132791: C813.1 R108.2 R836.1 U524.2(VFB)
N30132852: C817.2 U524.4(SS)
N30132884: R835.2 U527.3(D)
N30132918: C818.2 U525.5(TADJ)
N30132924: C819.2 U526.5(TADJ)
N30133027: R837.2 U528.3(D)
N30133077: C820.1 U59.1(dV/dT)
N30133183: R838.1 U59.10(ILIM)
N30178636: R872.2 U538.3(IN+) VR1.2(WIPER)
N30178648: C832.2 J532.1 R873.1
N30178650: J532.2 R874.1 TP279.1 U538.2(IN-)
N30178830: R876.2 U566.5(IN+) VR2.2(WIPER)
N30178842: C834.2 J533.1 R877.1
N30178844: J533.2 R878.1 TP281.1 U566.6(IN-)
N30179022: R880.2 U539.3(IN+) VR3.2(WIPER)
N30179034: C836.2 J535.1 R881.1
N30179036: J535.2 R882.1 TP283.1 U539.2(IN-)

Not connected (* = marked no-connect by the designer): SW5 2(nc2)* 4(nc4)* 6(nc6)*; U11 1*; U58 1*; U59 9(NC9)*; U520 1*; U525 8(FLAG1)*; U529 1*; U555 29(VLIN1)*; U556 26(GDC)* 29(VLIN1)* 33(GD2)*; U557 26(GDC)* 29(VLIN1)* 33(GD2)*; U568 1*; U569 1*

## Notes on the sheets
sheet 6
- For Texas Instruments Development Only
- BALLAST CONTROL
- 3
- B
- C
- E
- 1
- 2
- (C) COPYRIGHT 2020
         Texas Instruments
        All Rights Reserved
sheet 7
- DNI
  Install to enable softstart
  to limit inrush current
- Trip at 13.64V
- Q506 was specifically
   selected to have a high
  gate threshold (>1.3V). Do
  not make
  substitution for Q506 without
   taking this into account..
- UVLO set to 10.8V
  Power failure threshold 4%
  lower than UVLO = 10.35 V
- DNI
- 12V UVLO Monitor and Back Current Prevention
- 19V Protection
- StandBy 3.3V Supply
- DNI
  Install to enable softstart
  to limit inrush current
- DLPC7540 SUPPLY SEQUENCING
- (C) COPYRIGHT 2020
         Texas Instruments
        All Rights Reserved
sheet 8
- Communications and Fan Control
- Motor Driver
- CW2 MOTOR DRIVE
- Only for Current Sense
- NOTE: This resistor value is dependant upon the CW motor used.
   The value range is 0.47 ohms to 2.2 ohms.
   The target vlotage range for the SENSE pin is 100-150mV
   when the CW is running at a stable speed.
- (C) COPYRIGHT 2020
         Texas Instruments
        All Rights Reserved
sheet 9
- CW Indices
- Communications and Fan Control
- Motor Driver
- CW1 MOTOR DRIVE
- Only for Current Sense
- NOTE: This resistor value is dependant upon the CW motor used.
   The value range is 0.47 ohms to 2.2 ohms.
   The target vlotage range for the SENSE pin is 100-150mV
   when the CW is running at a stable speed.
- (C) COPYRIGHT 2020
         Texas Instruments
        All Rights Reserved
sheet 10
- 1.8V @ 3.7A
- 1.21V @ 5A?
- P2P5 Regulator Option for P1P21V Source
- 3.3V @ 1.6 A
- Communications and Fan Control
- Motor Driver
- Need SSP bus number for 7540
  Need connector info
- Only for Current Sense
- CW0 MOTOR DRIVE
- NOTE: This resistor value is dependant upon the CW motor used.
   The value range is 0.47 ohms to 2.2 ohms.
   The target vlotage range for the SENSE pin is 100-150mV
   when the CW is running at a stable speed.
- (C) COPYRIGHT 2020
         Texas Instruments
        All Rights Reserved
